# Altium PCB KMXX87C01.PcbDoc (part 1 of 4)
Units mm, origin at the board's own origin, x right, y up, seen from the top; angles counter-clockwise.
Board outline 109.2 x 85.1 mm, 4 copper layers (Top Layer, Mid-Layer 1, Mid-Layer 2, Bottom Layer); 294 components, 222 nets, 951 pads, 352 vias.
Unrouted connection lines stored in the file: 266.
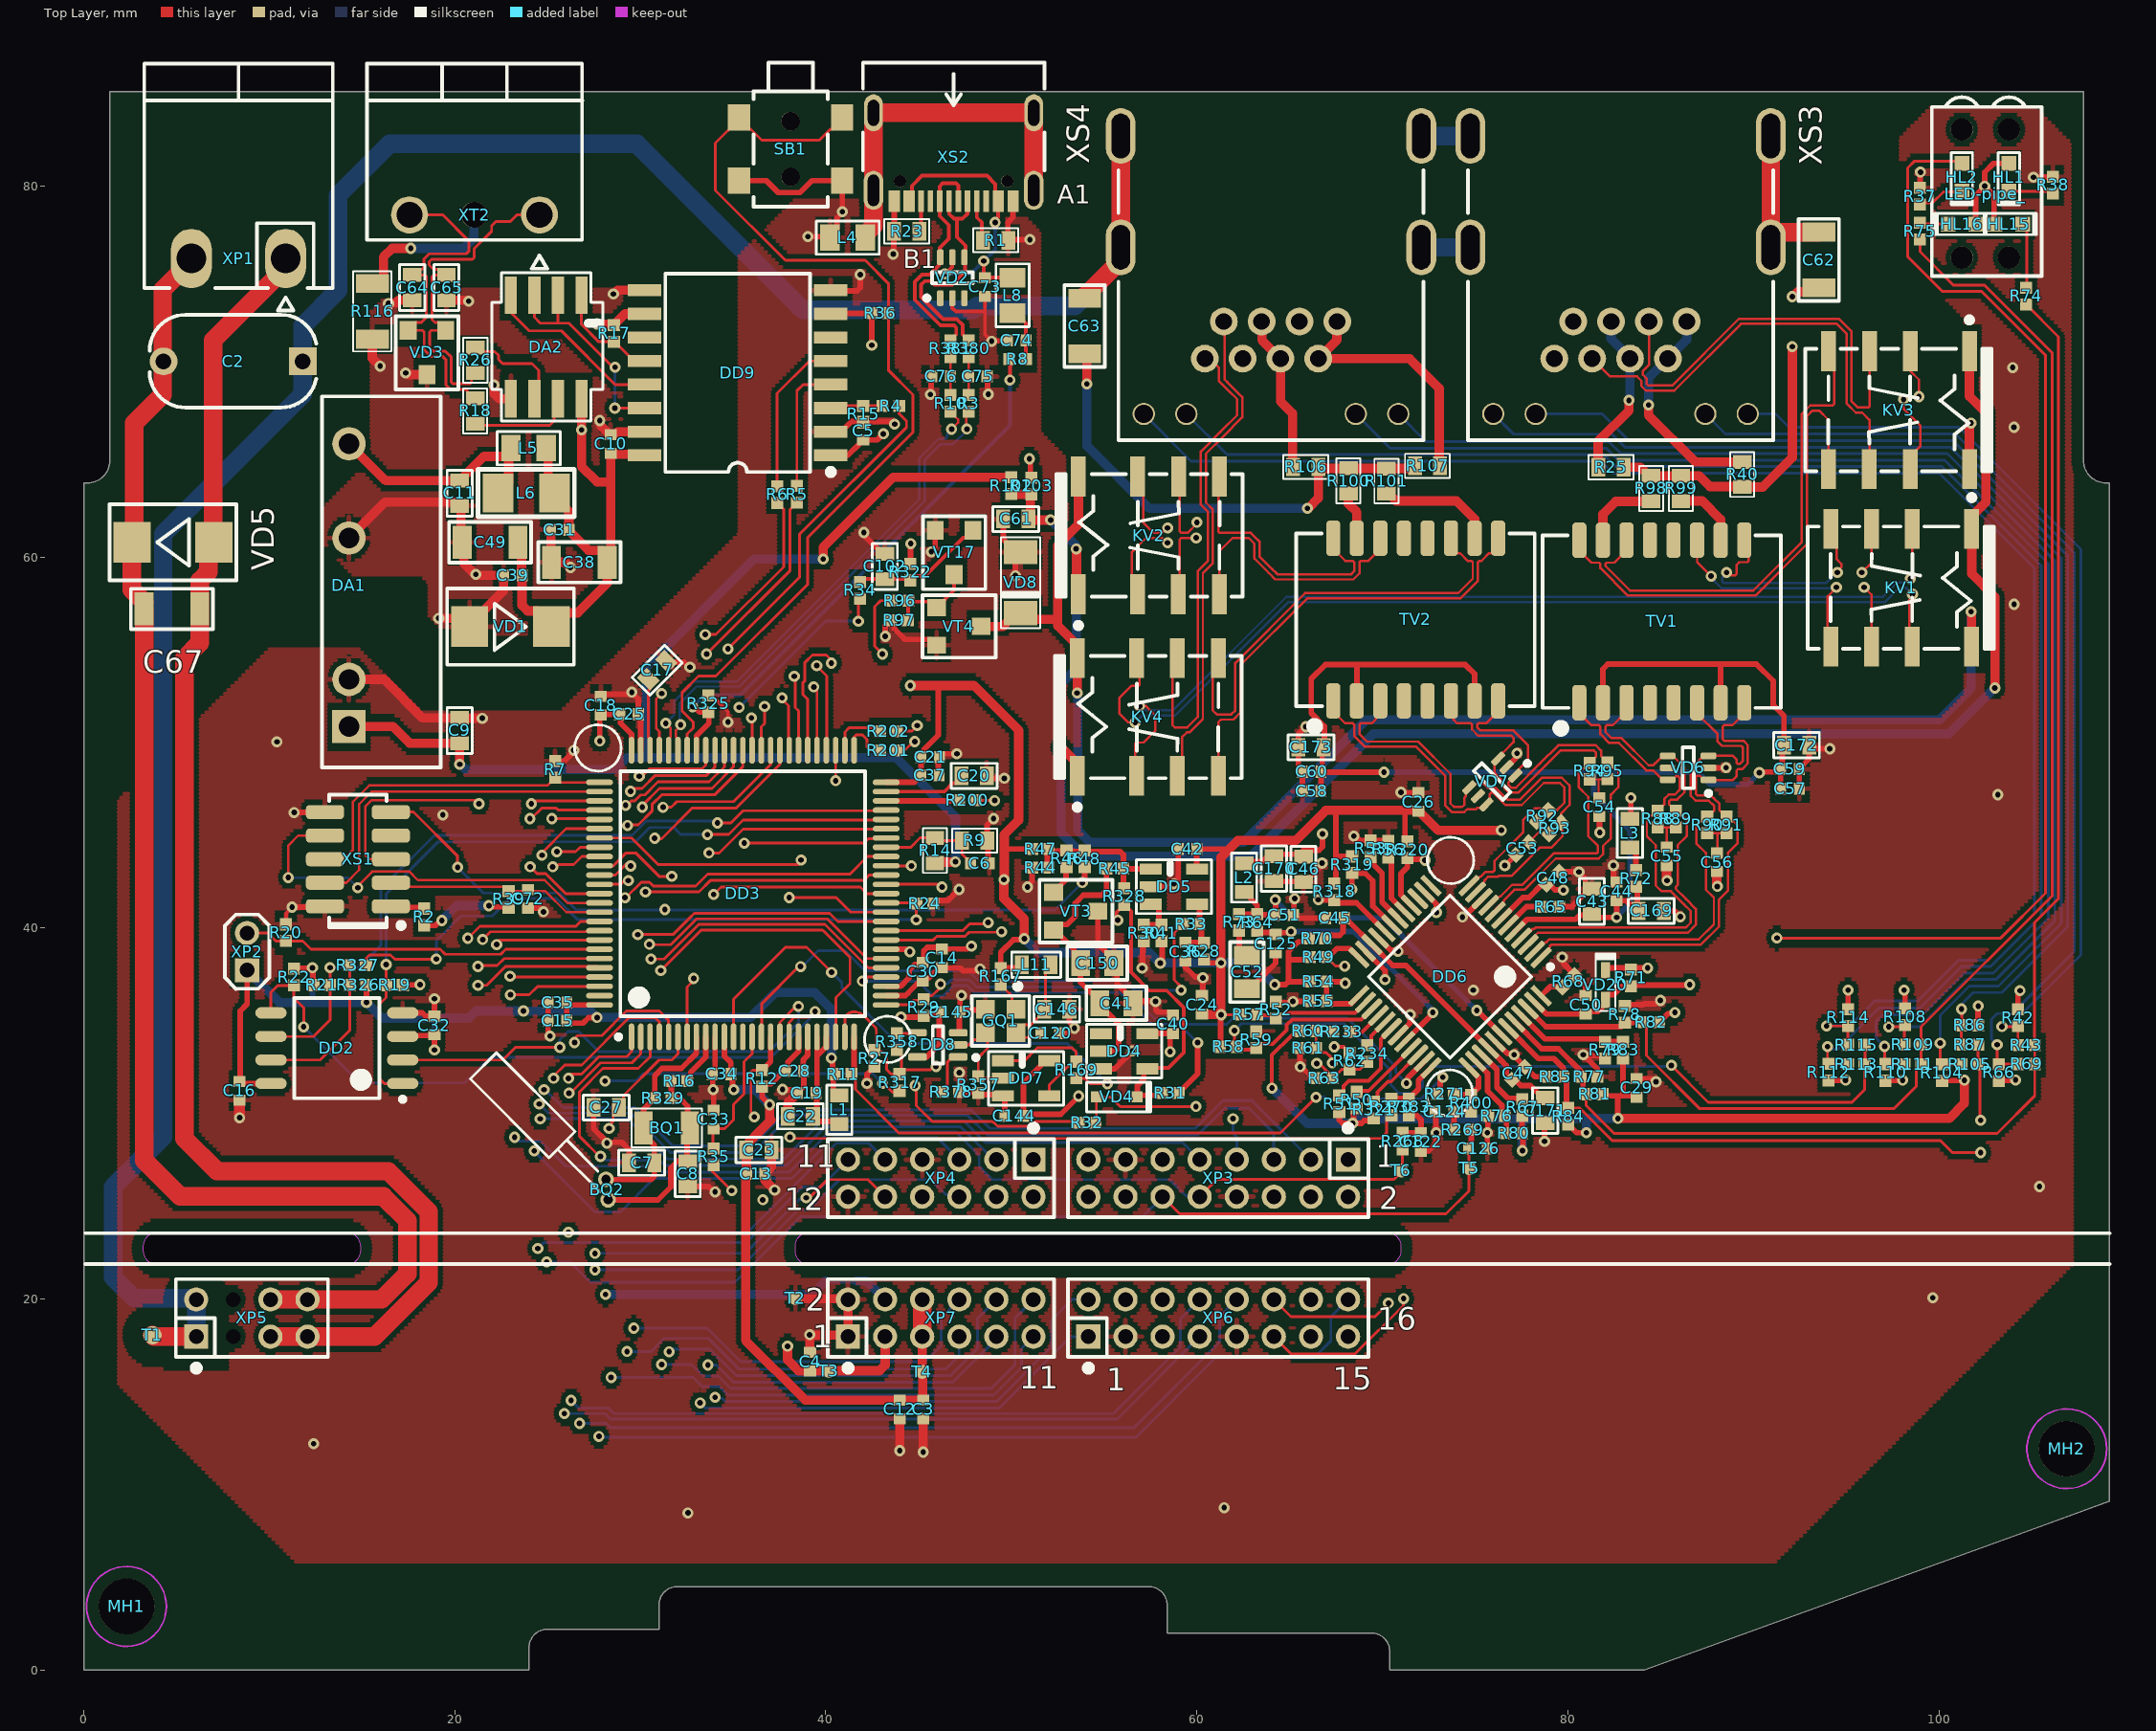
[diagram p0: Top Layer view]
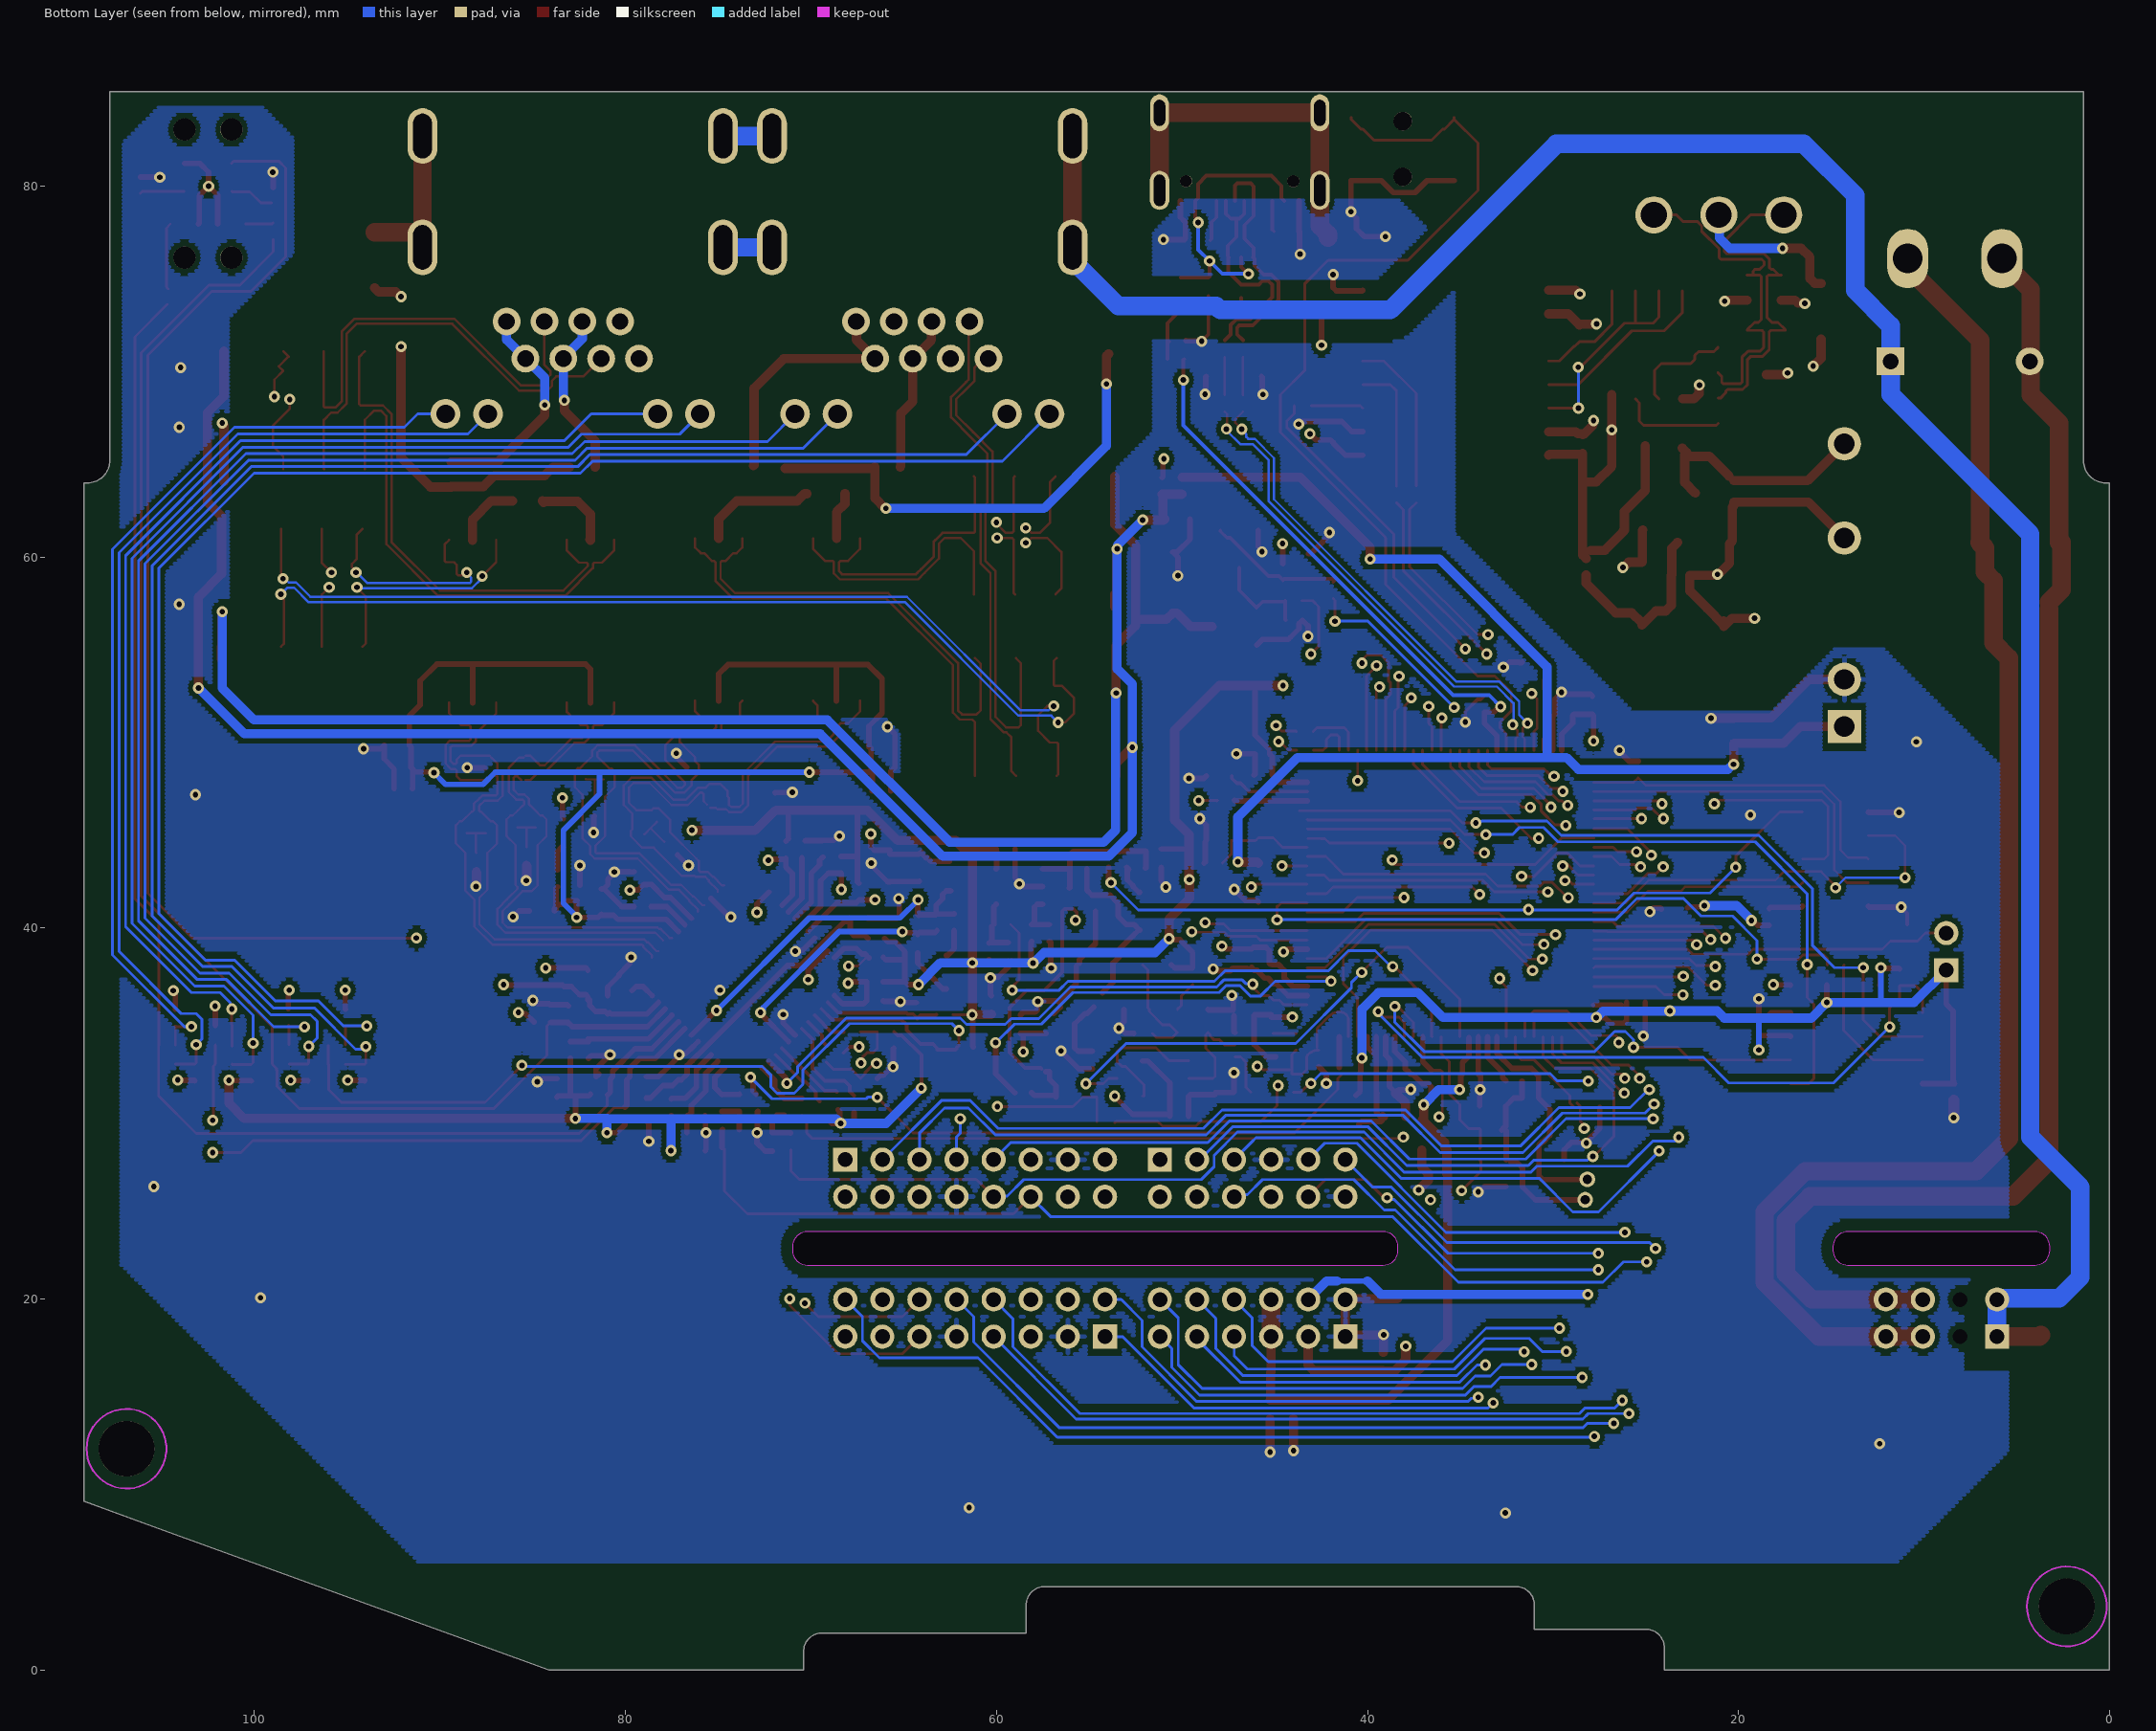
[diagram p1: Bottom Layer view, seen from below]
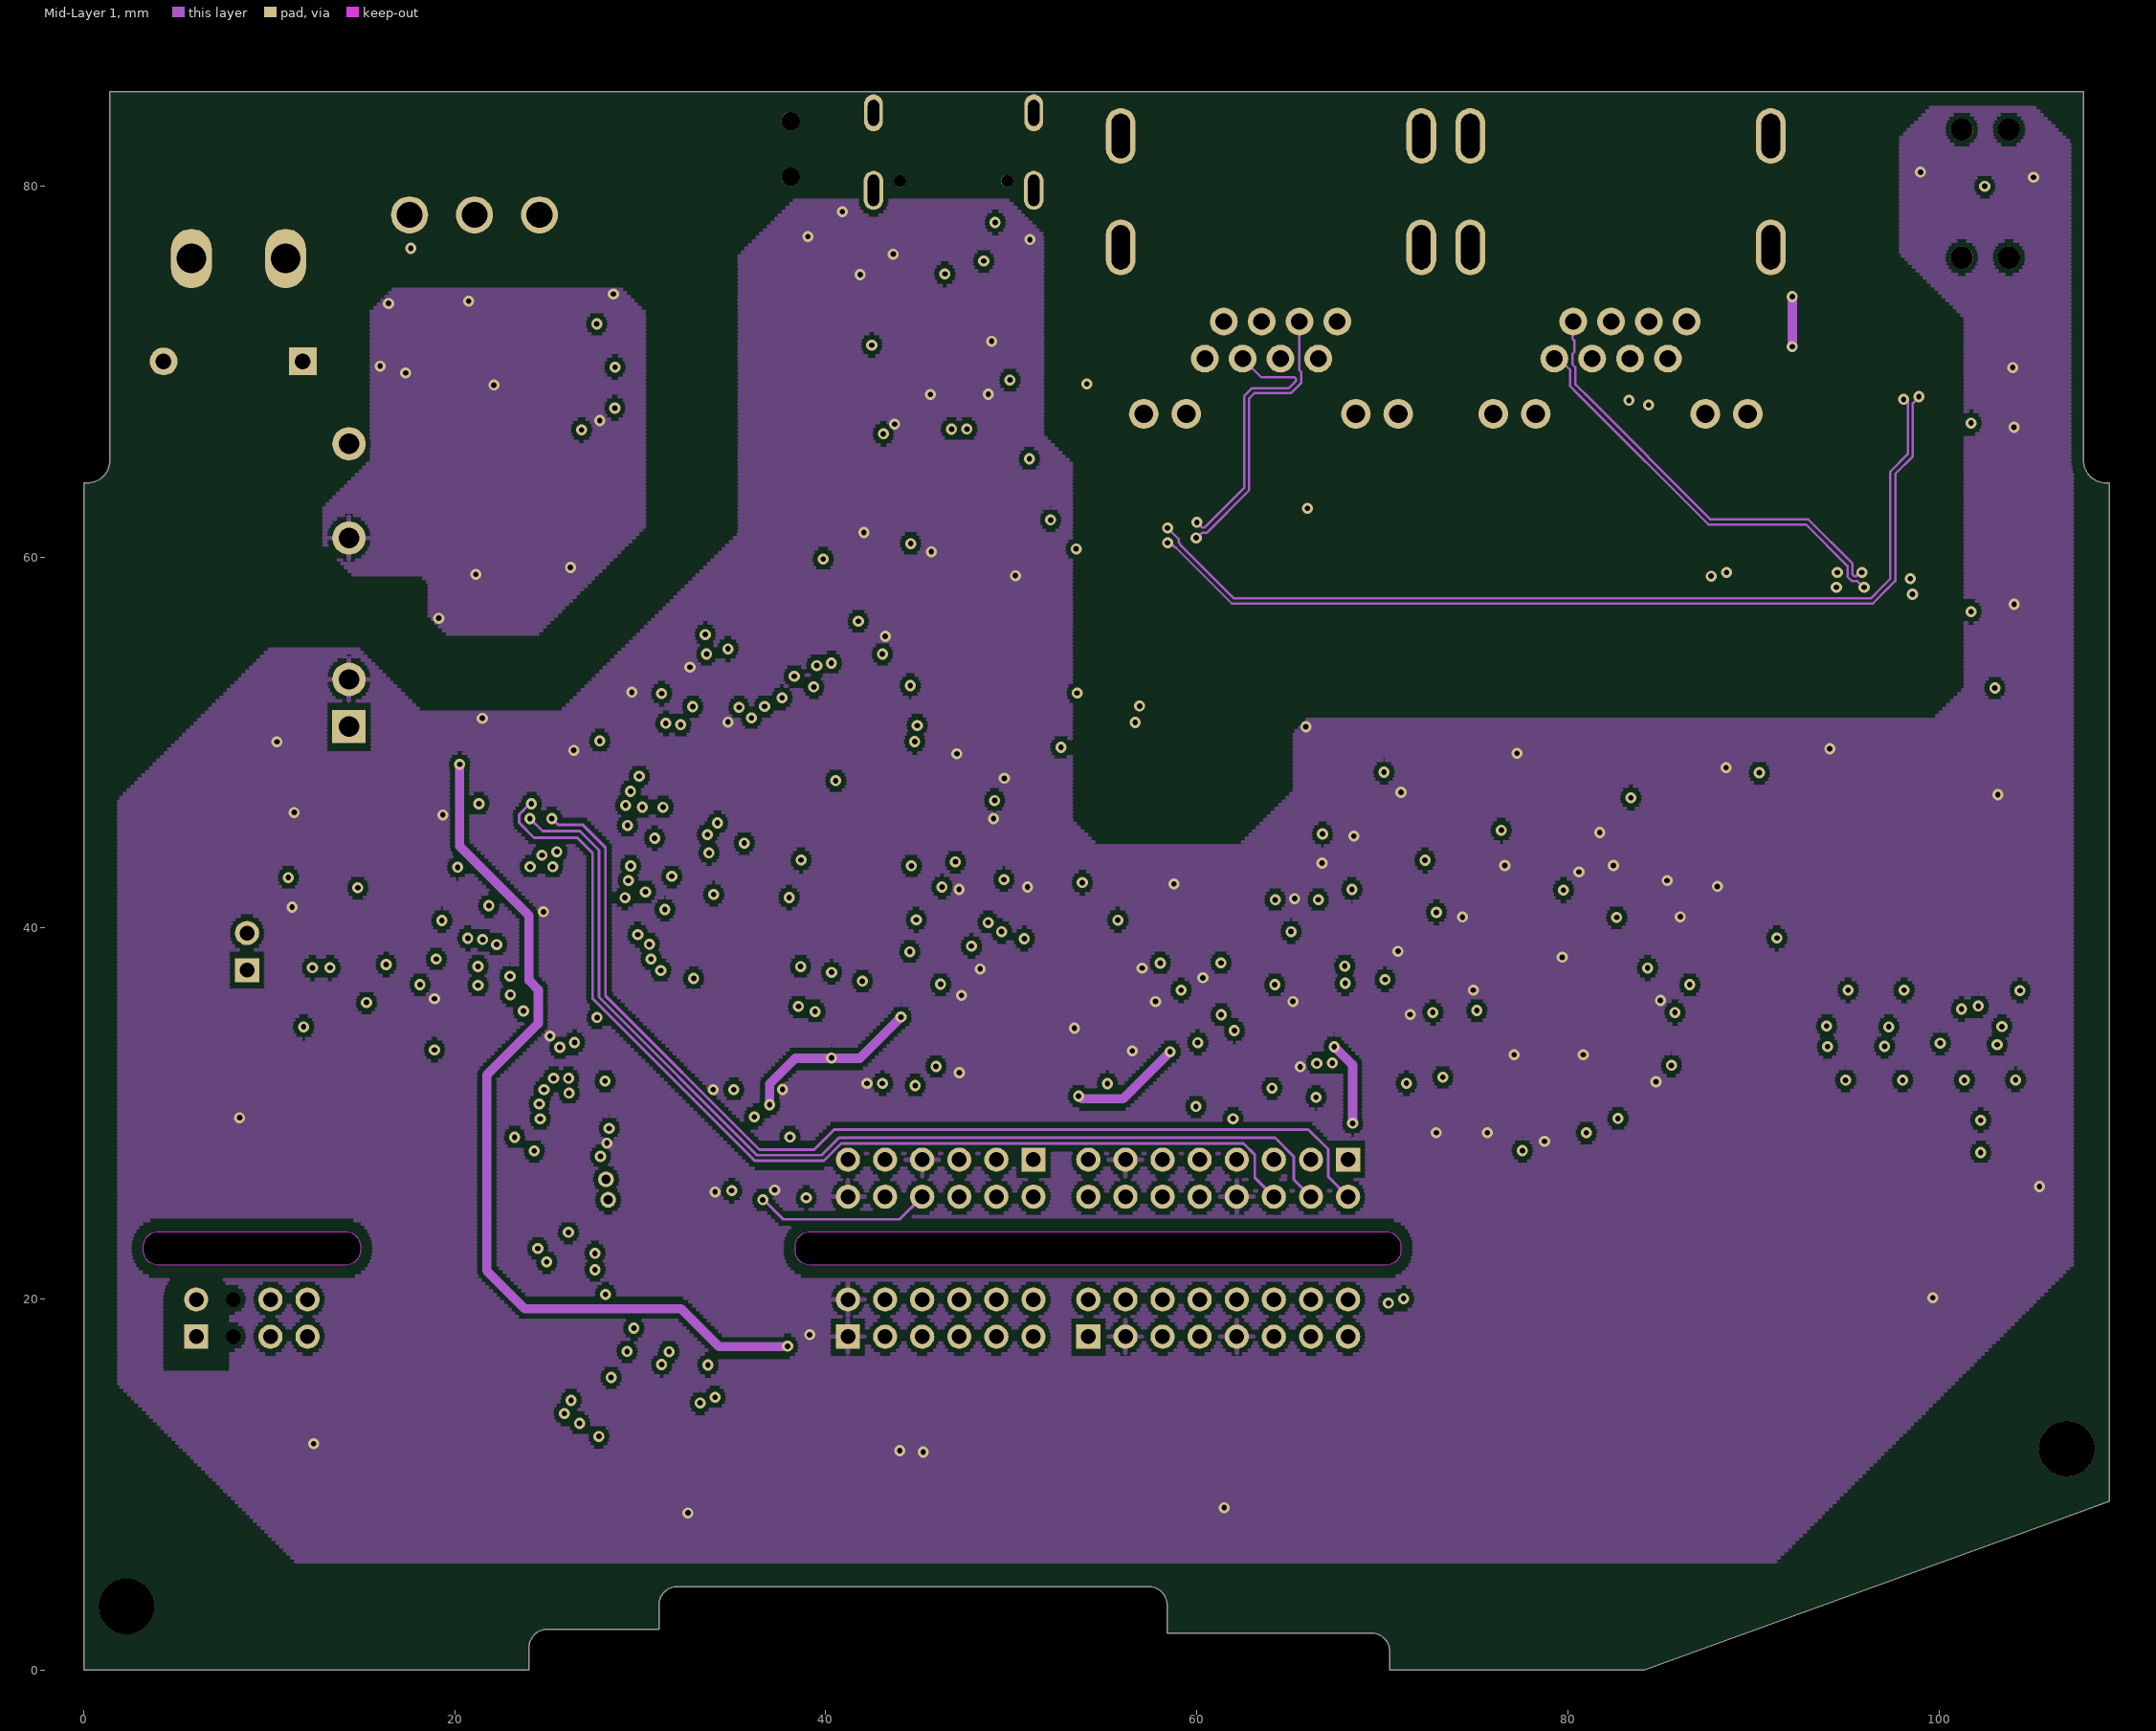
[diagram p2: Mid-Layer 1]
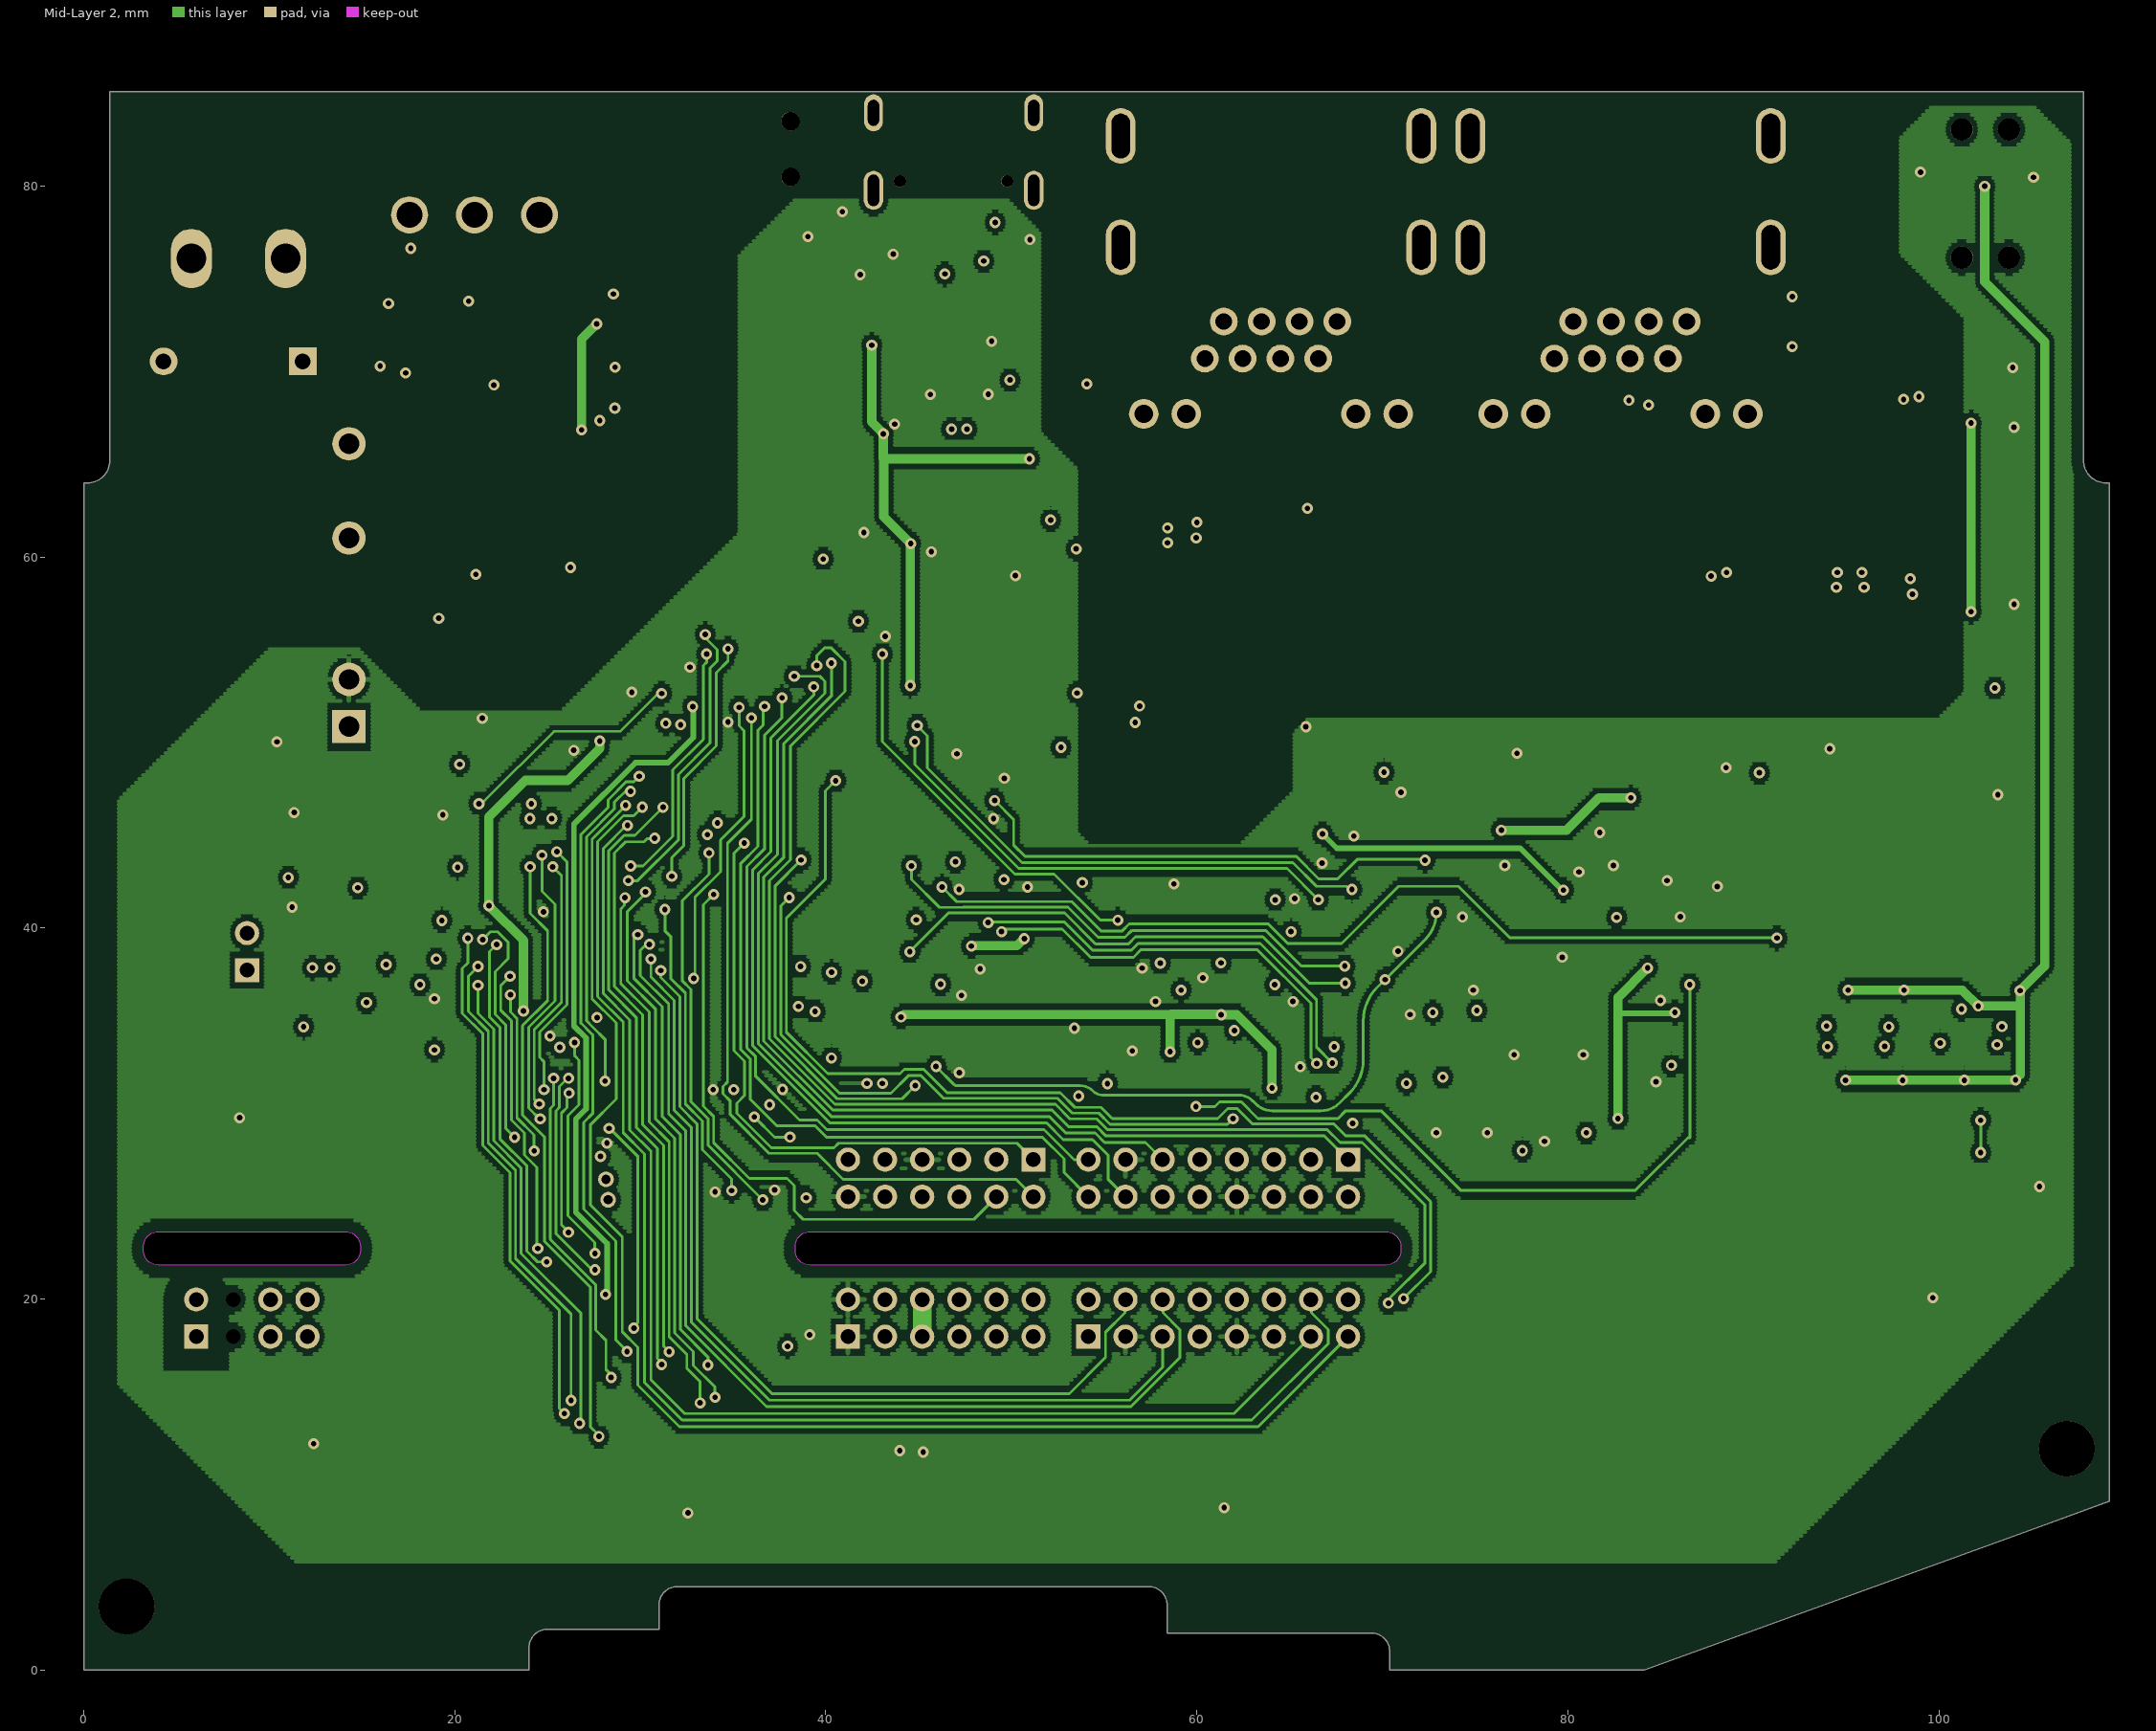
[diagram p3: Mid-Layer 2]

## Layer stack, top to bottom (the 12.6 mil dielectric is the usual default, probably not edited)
Top Solder: solder mask 0.0102, Solder Resist, Dk 3.5
Top Layer: signal copper 0.0356
Dielectric 1: core 0.32, FR-4, Dk 4.8
Mid-Layer 1: signal copper 0.0356
Dielectric2: prepreg 0.32, FR-4, Dk 4.8
Mid-Layer 2: signal copper 0.0356
Dielectric 3: core 0.32, FR-4, Dk 4.8
Bottom Layer: signal copper 0.0356
Bottom Solder: solder mask 0.0102, Solder Resist, Dk 3.5

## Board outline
0,0 24,0 24,1.2 cw(c25,1.2) 25,2.2 31,2.2 31,3.5 cw(c32,3.5) 32,4.5 57.4,4.5 cw(c57.4,3.5) 58.4,3.5 58.4,2 69.4,2 cw(c69.4,1) 70.4,1 70.4,0 84.124,0 105.476,7.748 109.2,9.1 109.2,64 109,64 cw(c109,65.2) 107.8,65.2 107.8,85.1 1.4,85.1 1.4,65.2 cw(c0.2,65.2) 0.2,64 0,64
cut-out: 39.15,21.826 cw(c39.15,22.626) 38.35,22.626 38.35,22.826 cw(c39.15,22.826) 39.15,23.626 70.198,23.626 cw(c70.198,22.826) 70.998,22.826 70.998,22.626 cw(c70.198,22.626) 70.198,21.826
cut-out: 4.015,21.826 cw(c4.015,22.626) 3.215,22.626 3.215,22.826 cw(c4.015,22.826) 4.015,23.626 14.105,23.626 cw(c14.105,22.826) 14.905,22.826 14.905,22.626 cw(c14.105,22.626) 14.105,21.826

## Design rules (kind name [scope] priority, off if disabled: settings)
AssemblyTestPointUsage [(ObjectKind = 'Pad') And (Component Like 'T*') And (AsMM(HoleDiameter) = 0) And (PadShape_AllLayers = 'Round') And ((AsMM(PadXSize_AllLayers) = 0.75) or (AsMM(PadXSize_AllLayers) = 0.991)) And ((AsMM(PadYSize_AllLayers) = 0.75) or (AsMM(PadYSize_AllLayers) = 0.991))] p1:
AssemblyTestpoint [All] p1 off: testpointundercomponent=TRUE minsize=0.75 maxsize=1 preferedsize=0.75 minholesize=0 maxholesize=0 preferedholesize=0 testpointgrid=0.025 usegrid=FALSE gridtolerance=0 allowsidetop=TRUE allowsidebottom=TRUE
BoardOutlineClearance [All    xor  ((Layer = 'BottomOverlay') or           (Layer = 'TopOverlay'))] p1: gap=0.6 ignorepadtopadclearanceinfootprint=FALSE
Clearance "Clearance TP to TP" [(Component Like 'T*') and (not (Component Like 'TV*')) vs (Component Like 'T*') and (not (Component Like 'TV*'))] p1: gap=1.75 ignorepadtopadclearanceinfootprint=FALSE except(0: Arc-Hole Track-Hole SMDPad-Hole THPad-Hole Via-Hole Fill-Hole Poly-Hole Region-Hole Text-Hole)
Clearance CHASSI_to_All [InNet('CHASSI') vs All xor ((ObjectKind = 'Track') And (Layer = 'KeepOutLayer') And (ObjectKind = 'Pad') And (Layer = 'MultiLayer') And (Net = 'No Net'))] p2: gap=1.1 ignorepadtopadclearanceinfootprint=FALSE except(0: Arc-Hole Track-Hole SMDPad-Hole THPad-Hole Via-Hole Fill-Hole Poly-Hole Region-Hole Text-Hole)
Clearance "Clearance_Board Outline" [OnLayer('Board Outline') vs (OnLayer('Mid-Layer 1') or OnLayer('Mid-Layer 2') ) xor ((ObjectKind = 'Pad') And ((Component <> 'SB1') or (Component <> 'XS2')) )] p3 off: gap=0.8 ignorepadtopadclearanceinfootprint=FALSE except(0: Arc-Hole Track-Hole SMDPad-Hole THPad-Hole Via-Hole Fill-Hole Poly-Hole Region-Hole Text-Hole)
Clearance "Clearance Via to Via" [IsVia vs IsVia] p4: gap=0.2 ignorepadtopadclearanceinfootprint=FALSE except(0: Arc-Hole Track-Hole SMDPad-Hole THPad-Hole Via-Hole Fill-Hole Poly-Hole Region-Hole Text-Hole)
Clearance "Clearance Pad to Via (exclude TP)" [IsPad and (not((ObjectKind = 'Pad') And ((Component Like 'T*') or (Component Like 'DA*')))) vs IsVia] p5: gap=0.2 ignorepadtopadclearanceinfootprint=FALSE except(0: Arc-Hole Track-Hole SMDPad-Hole THPad-Hole Via-Hole Fill-Hole Poly-Hole Region-Hole Text-Hole)
Clearance "Clearance Polygon to All" [InPolygon] p6: gap=0.25 ignorepadtopadclearanceinfootprint=FALSE except(0: Arc-Hole Track-Hole SMDPad-Hole THPad-Hole Via-Hole Fill-Hole Poly-Hole Region-Hole Text-Hole)
Clearance Clearance_'RS485' [InNetClass('RS485') vs InNetClass('All Nets')  xor    InNetClass('RS485')] p7: gap=2 ignorepadtopadclearanceinfootprint=FALSE except(0: Arc-Hole Track-Hole SMDPad-Hole THPad-Hole Via-Hole Fill-Hole Poly-Hole Region-Hole Text-Hole)
Clearance Clearance_'Ethernet [InNetClass('Ethernet') vs (InNetClass('All Nets')) xor (InNetClass('Ethernet'))] p8: gap=1.1 ignorepadtopadclearanceinfootprint=FALSE except(0: Arc-Hole Track-Hole SMDPad-Hole THPad-Hole Via-Hole Fill-Hole Poly-Hole Region-Hole Text-Hole)
Clearance "Clearance_All to All" [All] p9: gap=0.15 ignorepadtopadclearanceinfootprint=FALSE
ComponentClearance [All] p1: gap=0.1 collisioncheckmode=3 verticalgap=0.1 showdistances=FALSE
DiffPairsRouting [InDifferentialPairClass('USB')] p1: maxlimit=0.15 minlimit=0.15 mostfreqgap=0.15 toplayer_minwidth=0.127 toplayer_maxwidth=0.127 toplayer_prefwidth=0.127 midlayer1_minwidth=0.127 midlayer1_maxwidth=0.127 midlayer1_prefwidth=0.127 midlayer2_minwidth=0.127 midlayer2_maxwidth=0.127 midlayer2_prefwidth=0.127 bottomlayer_minwidth=0.127 bottomlayer_maxwidth=0.127 bottomlayer_prefwidth=0.127 maxuncoupledlength=12.7
DiffPairsRouting DiffPairsRouting_Eth_IN [All] p2: maxlimit=0.5 minlimit=0.15 mostfreqgap=0.15 toplayer_minwidth=0.127 toplayer_maxwidth=0.381 toplayer_prefwidth=0.127 midlayer1_minwidth=0.127 midlayer1_maxwidth=0.381 midlayer1_prefwidth=0.127 midlayer2_minwidth=0.127 midlayer2_maxwidth=0.381 midlayer2_prefwidth=0.127 bottomlayer_minwidth=0.127 bottomlayer_maxwidth=0.381 bottomlayer_prefwidth=0.127 maxuncoupledlength=12.7
FabricationTestPointUsage [All] p1 off: valid=0 allowmultiple=FALSE
FabricationTestpoint [All] p1 off: side=3 testpointundercomponent=TRUE minsize=1.016 maxsize=2.54 preferedsize=1.524 minholesize=0 maxholesize=1.016 preferedholesize=0.813 testpointgrid=0.025 allowsidetop=TRUE allowsidebottom=TRUE usegrid=TRUE gridtolerance=0
FanoutControl Fanout_BGA [IsBGA] p1 off: bgadir=Out bgaviamode=Centered fanoutstyle=Auto fanoutdirection=Alternating viagrid=0.025 // Fanout_BGA (Default Rule)
FanoutControl Fanout_LCC [IsLCC] p2 off: bgadir=Out bgaviamode=Centered fanoutstyle=Auto fanoutdirection=Alternating viagrid=0.025 // Fanout_LCC (Default Rule)
FanoutControl Fanout_SOIC [IsSOIC] p3 off: bgadir=Out bgaviamode=Centered fanoutstyle=Auto fanoutdirection=Alternating viagrid=0.025 // Fanout_SOIC (Default Rule)
FanoutControl Fanout_Small [(CompPinCount < 5)] p4 off: bgadir=Out bgaviamode=Centered fanoutstyle=Auto fanoutdirection=OutThenIn viagrid=0.025 // Fanout_Small (Default Rule)
FanoutControl Fanout_Default [All] p5 off: bgadir=Out bgaviamode=Centered fanoutstyle=Auto fanoutdirection=Alternating viagrid=0.025 // Fanout_Default (Default Rule)
Height [All] p1 off: minheight=0 maxheight=25.4 prefheight=12.7
HoleSize [All] p1 off: absolutevalues=TRUE maxlimit=2.54 minlimit=0.025 maxpercent=80.000 minpercent=20.000
HoleToHoleClearance [All] p1 off: gap=0.7 allowstackedmicrovias=TRUE
MinimumSolderMaskSliver [All] p1 off: minsoldermaskwidth=0.2
PasteMaskExpansion [All] p1: expansion=-0.03
PlaneClearance [All] p1: clearance=0.5
PlaneConnect [All] p1: planeconnectstyle=Relief reliefexpansion=0.5 reliefentries=4 reliefconductorwidth=0.2 reliefairgap=0.2
PolygonConnect PolygonConnect_Via [IsVia] p1: connectstyle=Direct reliefconductorwidth=0.254 reliefentries=4 polygonreliefangle="90 Angle" airgapwidth=0.254
PolygonConnect PolygonConnect_power [InPadClass('Term')] p2: connectstyle=Direct reliefconductorwidth=0.254 reliefentries=4 polygonreliefangle="90 Angle" airgapwidth=0.254
PolygonConnect PolygonConnect_0.6 [InPadClass('0.6')] p3: connectstyle=Relief reliefconductorwidth=0.6 reliefentries=4 polygonreliefangle="90 Angle" airgapwidth=0.3
PolygonConnect PolygonConnect_1.0 [InPadClass('1.0')] p4: connectstyle=Relief reliefconductorwidth=0.6 reliefentries=4 polygonreliefangle="90 Angle" airgapwidth=0.3
PolygonConnect "PolygonConnect to Thermal components" [(InComponentClass('Thermal connect'))] p5: connectstyle=Relief reliefconductorwidth=0.25 reliefentries=4 polygonreliefangle="90 Angle" airgapwidth=0.25
PolygonConnect PolygonConnect_All [All] p6: connectstyle=Relief reliefconductorwidth=0.25 reliefentries=4 polygonreliefangle="90 Angle" airgapwidth=0.25
RoutingVias [All] p1: holewidth=0.4 width=0.8 viastyle="Through Hole" minholewidth=0.2 minwidth=0.4 maxholewidth=0.8 maxwidth=1.5
SilkToSilkClearance [All] p1: silktosilkclearance=0.1
SilkToSolderMaskClearance SilkscreenOverComponentPads [IsPad] p1: minsilkscreentomaskgap=0.1 clearancetoexposedcopper=TRUE
SolderMaskExpansion Via_0.6x0.3_NoMask [(ObjectKind = 'Via') And (ViaDiameter = AsMM(0.6)) And (HoleDiameter = AsMM(0.3))] p1: expansion=-20 istentingtop=FALSE
SolderMaskExpansion [All] p2: expansion=0 istentingtop=FALSE
Width [All] p1: maxlimit=10 minlimit=0.127 preferedwidth=0.2
10 further rules are at their usual default settings.

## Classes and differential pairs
net class RS485: 5V_RS GND_RS NetC11_1 NetDA2_1 NetDA2_2 NetDA2_4 NetDA2_6 NetDA2_7 NetR116_2 RS485_N RS485_P
net class Ethernet: ETH1_RX_N ETH1_RX_P ETH1_TX_N ETH1_TX_P ETH2_RX_N ETH2_RX_P ETH2_TX_N ETH2_TX_P NetC62_1 NetC63_1 NetR25_2 NetR40_2 NetR98_2 NetR99_2 NetR100_2 NetR101_2 NetR106_2 NetR107_2 RX_N RX_P TV1_RX_N TV1_RX_P TV1_TX_N TV1_TX_P TV2_RX_N TV2_RX_P TV2_TX_N TV2_TX_P TX_N TX_P
component class RS-485: C5 C9 C10 C11 C31 C38 C39 C49 C64 C65 DA1 DA2 DD9 L5 L6 R4 R5 R6 R15 R17 R18 R26 VD1 VD3
component class KMXX87C01_Main: C2 C3 C4 C62 C63 C67 L4 R1 R2 R23 R25 R40 R42 R43 R66 R69 R86 R87 R104 R105 R106 R107 R108 R109 R110 R111 R112 R113 R114 R115 R116 T1 T2 T3 T4 T5 T6 VD5 XP1 XP3 XP4 XP5 XP6 XP7 XS1 XS2 XS3 XS4 XT2
component class Ethernet: C43 C44 C45 C46 C47 C48 C50 C51 C52 C53 C54 C55 C56 C57 C58 C59 C60 C61 C102 C122 C124 C125 C126 C169 C170 C171 C172 C173 DD6 HL15 HL16 KV1 KV2 KV3 KV4 L2 L3 R34 R49 R50 R51 R52 R53 R54 R55 R56 R57 R58 R59 R60 R61 R62 R63 R64 R65 R67 R68 R70 R71 R72 R73 R74 R75 R76 R77 R78 R79 R80 R81 R82 R83 R84 R85 R88 R89 R90 R91 R92 R93 R94 R95 R96 R97 R98 R99 R100 R101 R102 R103 R106 R107 R108 R109 R110 R111 R114 R233 R234 R268 R269 R270 R271 R318 R319 R320 R321 R322 R383 R400 TV1 TV2 VD6 VD7 VD8 VD20 VT4 VT17
component class CPU: BQ1 BQ2 C6 C7 C8 C12 C13 C14 C15 C16 C17 C18 C19 C20 C21 C22 C23 C24 C25 C26 C27 C28 C29 C30 C32 C33 C34 C35 C36 C37 C40 C41 C42 C72 C73 C74 C75 C76 C120 C144 C145 C146 C150 DD2 DD3 DD4 DD5 DD7 DD8 GQ1 HL1 HL2 L1 L8 L11 R3 R7 R8 R9 R10 R11 R12 R14 R16 R19 R20 R21 R22 R24 R27 R28 R29 R30 R31 R32 R33 R35 R36 R37 R38 R39 R41 R44 R45 R46 R47 R48 R167 R200 R201 R202 R317 R325 R326 R327 R328 R329 R357 R358 R378 R380 R381 SB1 VD2 VD4 VT3 XP2
net class CHASSI: CHASSI
differential pair ETH2_TX: +ETH2_TX_P -ETH2_TX_N
differential pair ETH2_RX: +ETH2_RX_P -ETH2_RX_N
differential pair OTG_FS_D: +OTG_FS_D_P -OTG_FS_D_N
differential pair TX: +TX_P -TX_N
differential pair TV2_TX: +TV2_TX_P -TV2_TX_N
differential pair TV2_RX: +TV2_RX_P -TV2_RX_N
differential pair TV1_TX: +TV1_TX_P -TV1_TX_N
differential pair TV1_RX: +TV1_RX_P -TV1_RX_N
differential pair TD2: +TD2_P -TD2_N
differential pair TD1: +TD1_P -TD1_N
differential pair RX: +RX_P -RX_N
differential pair RS485: +RS485_P -RS485_N
differential pair RD2: +RD2_P -RD2_N
differential pair RD1: +RD1_P -RD1_N
differential pair ETH1_TX: +ETH1_TX_P -ETH1_TX_N
differential pair ETH1_RX: +ETH1_RX_P -ETH1_RX_N
differential pair D1: +D1_P -D1_N

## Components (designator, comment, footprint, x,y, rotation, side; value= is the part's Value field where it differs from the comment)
BQ1 "NX3215SA-32,768kHz±10ppm(25C)/±170ppm(-40/+85C)/6" NX3215SA 31.425,29.225 r180 top
BQ2 "MMTF32-32,768kHz±20ppm(25C)/±170ppm(-40/+85C)/6pF" MMTF32 28.15,26.454 r315 top locked
C2 "CS-JY-Y2-1000пФ-20%-Y5U (Murata, 7.0x5.0x7.5)" JY_8-A2 8.05,70.55 r180 top
C3 "C0402-16В-0,1мкФ-10%-X7R (Walsin, 0402B104K160CT)" C0402 45.25,14.05 r270 top
C4 "C0402-16В-0,1мкФ-10%-X7R (Walsin, 0402B104K160CT)" C0402 39.15,16.625 r270 top
C5 "C0402-16В-0,1мкФ-10%-X7R (Samsung, CL05B104KO5NNNC" C0402 42.015,66.817 r270 top
C6 "C0402-50В-0,01мкФ-10%-X7R (Walsin, 0402B103K500CT)" C0402 48.306,43.499 r0 top
C7 "C0603-50В-4,7пФ-0,25пФ-NPO (Walsin, 0603N4R7C500CT)" CC0603-KL 30.075,27.35 r180 top
C8 "C0603-50В-4,7пФ-0,25пФ-NPO (Walsin, 0603N4R7C500CT)" CC0603-KL 32.55,26.75 r270 top
C9 "C0603-25В-1,0мкФ-10%-X7R (Samsung, CL10B105KA8NNNC" CC0603-KL 20.262,50.65 r90 top
C10 "C0402-16В-0,1мкФ-10%-X7R (Samsung, CL05B104KO5NNNC" C0402 28.4,66.1 r270 top
C11 "C0603-25В-1,0мкФ-10%-X7R (Samsung, CL10B105KA8NNNC" CC0603-KL 20.262,63.442 r270 top
C12 "C0402-50В-220пФ-5%-NPO (Walsin, 0402N221J500CT)" C0402 43.995,14.05 r270 top
C13 "C0402-50В-220пФ-5%-NPO (Walsin, 0402N221J500CT)" C0402 36.225,26.75 r0 top
C14 "C0402-50В-220пФ-5%-NPO (Walsin, 0402N221J500CT)" C0402 46.25,38.375 r270 top
C15 "C0402-50В-220пФ-5%-NPO (Walsin, 0402N221J500CT)" C0402 25.531,35.001 r180 top
C16 "C0402-16В-0,1мкФ-10%-X7R (Walsin, 0402B104K160CT)" C0402 8.4,31.225 r270 top
C17 "C0603-10В-2,2мкФ-10%-X7R (Samsung, CL10B225KP8NNNC" CC0603-KL 30.912,53.9 r45 top
C18 "C0402-50В-220пФ-5%-NPO (Walsin, 0402N221J500CT)" C0402 27.875,52 r90 top
C19 "C0402-50В-0,01мкФ-10%-X7R (Walsin, 0402B103K500CT)" C0402 38.975,31.1 r180 top
C20 "C0603-10В-2,2мкФ-10%-X7R (Samsung, CL10B225KP8NNNC" CC0603-KL 47.996,48.204 r0 top
C21 "C0402-50В-220пФ-5%-NPO (Walsin, 0402N221J500CT)" C0402 45.625,49.225 r0 top
C22 "C0603-25В-1,0мкФ-10%-X7R (Samsung, CL10B105KA8NNNC" CC0603-KL 38.625,29.85 r180 top
C23 "C0603-6,3В-4,7мкФ-10%-X5R (Samsung, CL10A475KQ8NNN" CC0603-KL 36.395,28.042 r0 top
C24 "C0402-50В-220пФ-5%-NPO (Walsin, 0402N221J500CT)" C0402 60.275,35.863 r90 top
C25 "C0402-16В-0,1мкФ-10%-X7R (Walsin, 0402B104K160CT)" C0402 29.387,51.525 r0 top
C26 "C0402-50В-220пФ-5%-NPO (Walsin, 0402N221J500CT)" C0402 71.948,46.8 r90 top
C27 "C0603-25В-1,0мкФ-10%-X7R (Samsung, CL10B105KA8NNNC" CC0603-KL 28.157,30.325 r180 top
C28 "C0402-16В-0,1мкФ-10%-X7R (Walsin, 0402B104K160CT)" C0402 38.311,32.29 r0 top
C29 "C0402-50В-220пФ-5%-NPO (Walsin, 0402N221J500CT)" C0402 83.7,31.385 r90 top
C30 "C0402-16В-0,1мкФ-10%-X7R (Walsin, 0402B104K160CT)" C0402 45.225,37.65 r270 top
C31 "C0402-16В-0,1мкФ-10%-X7R (Samsung, CL05B104KO5NNNC" C0402 25.65,61.475 r0 top
C32 "C0402-50В-220пФ-5%-NPO (Walsin, 0402N221J500CT)" C0402 18.9,34.75 r90 top
C33 "C0402-50В-0,01мкФ-10%-X7R (Walsin, 0402B103K500CT)" C0402 33.954,29.678 r90 top
C34 "C0402-16В-0,1мкФ-10%-X7R (Walsin, 0402B104K160CT)" C0402 34.38,32.128 r180 top
C35 "C0402-16В-0,1мкФ-10%-X7R (Walsin, 0402B104K160CT)" C0402 25.531,35.989 r180 top
C36 "C0402-50В-0,01мкФ-10%-X7R (Walsin, 0402B103K500CT)" C0402 59.376,38.725 r270 top
C37 "C0402-16В-0,1мкФ-10%-X7R (Walsin, 0402B104K160CT)" C0402 45.61,48.244 r0 top
C38 "C1206-16В-10мкФ-10%-X7R (Samsung, CL31B106KOHNNNE)" CC1206-KL 26.714,59.725 r0 top
C39 "C0402-16В-0,1мкФ-10%-X7R (Samsung, CL05B104KO5NNNC" C0402 23.127,59.017 r0 top
C40 "C0402-16В-0,1мкФ-10%-X7R (Walsin, 0402B104K160CT)" C0402 58.712,34.813 r90 top
C41 "C0805-16В-10мкФ-10%-X5R (Walsin, 0805X106K160CT)" CC0805-KL 55.66,35.938 r180 top
C42 "C0402-16В-0,1мкФ-10%-X7R (Walsin, 0402B104K160CT)" C0402 59.5,44.266 r180 top
C43 "C0603-25В-1,0мкФ-10%-X7R (Samsung, CL10B105KA8NNNC" CC0603-KL 81.296,41.436 r90 top
C44 "C0402-16В-0,1мкФ-10%-X7R (Walsin, 0402B104K160CT)" C0402 82.615,41.981 r90 top
C45 "C0402-16В-0,1мкФ-10%-X7R (Walsin, 0402B104K160CT)" C0402 67.443,40.537 r180 top
C46 "C0603-25В-1,0мкФ-10%-X7R (Samsung, CL10B105KA8NNNC" CC0603-KL 65.746,43.175 r270 top
C47 "C0402-16В-0,1мкФ-10%-X7R (Walsin, 0402B104K160CT)" C0402 77.337,32.166 r45 top
C48 "C0402-16В-0,1мкФ-10%-X7R (Walsin, 0402B104K160CT)" C0402 79.182,42.691 r45 top
C49 "C1206-16В-10мкФ-10%-X7R (Samsung, CL31B106KOHNNNE)" CC1206-KL 21.9,60.8 r0 top
C50 "C0402-50В-0,01мкФ-10%-X7R (Walsin, 0402B103K500CT)" C0402 80.962,35.863 r90 top
C51 "C0402-16В-0,1мкФ-10%-X7R (Walsin, 0402B104K160CT)" C0402 64.702,40.693 r0 top
C52 "C0805-16В-10мкФ-10%-X5R (Walsin, 0805X106K160CT)" CC0805-KL 62.7,37.624 r90 top
C53 "C0402-16В-0,1мкФ-10%-X7R (Walsin, 0402B104K160CT)" C0402 77.55,44.292 r225 top
C54 "C0402-16В-0,1мкФ-10%-X7R (Walsin, 0402B104K160CT)" C0402 81.689,46.524 r270 top
C55 "C0402-16В-0,1мкФ-10%-X7R (Walsin, 0402B104K160CT)" C0402 85.331,43.872 r270 top
C56 "C0402-16В-0,1мкФ-10%-X7R (Walsin, 0402B104K160CT)" C0402 88.035,43.546 r270 top
C57 "C0402-16В-0,1мкФ-10%-X7R (Walsin, 0402B104K160CT)" C0402 91.978,47.514 r0 top
C58 "C0402-16В-0,1мкФ-10%-X7R (Walsin, 0402B104K160CT)" C0402 66.19,47.38 r180 top
C59 "C0402-16В-0,1мкФ-10%-X7R (Walsin, 0402B104K160CT)" C0402 91.973,48.564 r0 top
C60 "C0402-16В-0,1мкФ-10%-X7R (Walsin, 0402B104K160CT)" C0402 66.19,48.43 r180 top
C61 "C0603-25В-1,0мкФ-10%-X7R (Samsung, CL10B105KA8NNNC" CC0603-KL 50.244,62.051 r180 top
C62 "C1206-2000B-1000пФ-10%-X7R (Walsin, 1206B102K202CT" CC1206-KL 93.525,76.02 r90 top
C63 "C1206-2000B-1000пФ-10%-X7R (Walsin, 1206B102K202CT" CC1206-KL 53.954,72.458 r90 top
C64 "Не устанавливать" CC0603-KL 17.698,74.527 r90 top
C65 "Не устанавливать" CC0603-KL 19.548,74.527 r90 top
C67 "C1206-100В-0,1мкФ-10%-X7R (Samsung, CL31B104KCFNNN" CC1206-KL 4.75,57.2 r0 top
C72 "C0402-50В-0,01мкФ-10%-X7R (Walsin, 0402B103K500CT)" C0402 23.95,41.575 r90 top
C73 "C0402-50В-0,01мкФ-10%-X7R (Walsin, 0402B103K500CT)" C0402 48.58,74.564 r90 top
C74 "C0402-16В-0,1мкФ-10%-X7R (Walsin, 0402B104K160CT)" C0402 50.289,71.672 r180 top
C75 "C0402-50В-33пФ-5%-NPO (Walsin, 0402N330J500CT)" C0402 48.19,69.738 r180 top
C76 "C0402-50В-33пФ-5%-NPO (Walsin, 0402N330J500CT)" C0402 46.215,69.738 r0 top
C102 "C0603-25В-1,0мкФ-10%-X7R (Samsung, CL10B105KA8NNNC" CC0603-KL 43.181,59.495 r90 top
C120 "C0402-50В-0,01мкФ-10%-X7R (Walsin, 0402B103K500CT)" C0402 52.1,34.328 r0 top
C122 "C0402-50В-10пФ-5%-NPO (Murata, GRM1555C1H100JA01D)" C0402 72.081,28.471 r270 top
C124 "C0402-50В-10пФ-5%-NPO (Murata, GRM1555C1H100JA01D)" C0402 73.362,30.107 r180 top
C125 "C0402-16В-0,1мкФ-10%-X7R (Walsin, 0402B104K160CT)" C0402 64.249,39.16 r270 top
C126 "C0402-16В-0,1мкФ-10%-X7R (Walsin, 0402B104K160CT)" C0402 75.162,28.107 r0 top
C144 "C0402-16В-0,1мкФ-10%-X7R (Walsin, 0402B104K160CT)" C0402 50.154,29.862 r180 top
C145 "C0402-16В-0,1мкФ-10%-X7R (Walsin, 0402B104K160CT)" C0402 46.744,35.468 r0 top
C146 "C0603-10В-2,2мкФ-10%-X7R (Samsung, CL10B225KP8NNNC" CC0603-KL 52.45,35.625 r0 top
C150 "C0805-16В-10мкФ-10%-X5R (Walsin, 0805X106K160CT)" CC0805-KL 54.629,38.104 r180 top
C169 "C0603-10В-10мкф-10%-X5R (Samsung, CL10A106KP8NNNC)" CC0603-KL 84.5,40.925 r0 top
C170 "C0603-10В-10мкф-10%-X5R (Samsung, CL10A106KP8NNNC)" CC0603-KL 64.153,43.208 r270 top
C171 "C0603-10В-10мкф-10%-X5R (Samsung, CL10A106KP8NNNC)" CC0603-KL 78.78,30.157 r270 top
C172 "C0603-10В-10мкф-10%-X5R (Samsung, CL10A106KP8NNNC)" CC0603-KL 92.328,49.864 r0 top
C173 "C0603-10В-10мкф-10%-X5R (Samsung, CL10A106KP8NNNC)" CC0603-KL 66.153,49.747 r180 top
DA1 "F0505S-1WR2" F0505S-1W 14.291,50.867 r90 top value="F0505S-1WR2 (Mornsun, SIP-5)"
DA2 "THVD1500DR (TI, SO-8)" SO8 24.925,71.325 r270 top
DD2 "MX25L3233FM2I-08G (Macronix, SO-8)" SOP127P790X216-8N 13.64,33.524 r180 top locked
DD3 "STM32F207VCT6 (STM, LQFP-100)" TSQFP50P1600X1600X160-100N 35.525,41.857 r90 top locked
DD4 "SN74LVC1G17DBV (Ti,SOT23-5)" SOT23-5 56.085,33.363 r180 top
DD5 "CAT823STDI-GT3 (Onsemi, SOT-23-5)" SOT23-5 58.766,42.232 r180 top
DD6 "KSZ8863RLLI (Micrel, LQFP-48)" TSQFP50P900X900X160-48N 73.65,37.378 r225 top locked
DD7 "SN74LVC1G80DBVR (TI, SOT23-5)" SOT23-5 50.8,31.9 r180 top
DD8 "SN74LVC1G125DCK (Ti, SC70-5)" SOT65P210-5N 46.038,33.704 r180 top locked
DD9 "ISO7331CDWR (TI, SO_W-16)" SO-16_W 35.25,69.938 r180 top
GQ1 "FXO2520-3,3V-50,000MHz±50ppm 15pF (Fronter)" FXO2520 49.425,34.993 r180 top
HL1 "HQ19-2132SYGC82 (HQG)" HT19-2132 103.779,80.476 r90 top
HL2 "HT19-2132SURC-С" HT19-2132 101.239,80.476 r90 top
HL15 "HQ19-2132SYGC82 (HQG)" HT19-2132 103.779,77.956 r180 top
HL16 "HQ19-2132SYGC82 (HQG)" HT19-2132 101.239,77.956 r0 top
KV1 "HFD4/5-SR (Hongfa)" "TE IM03GR Gul wings" 97.975,58.349 r180 top locked
KV2 "HFD4/5-SR (Hongfa)" "TE IM03GR Gul wings" 57.417,61.17 r0 top locked
KV3 "HFD4/5-SR (Hongfa)" "TE IM03GR Gul wings" 97.85,67.925 r180 top locked
KV4 "HFD4/5-SR (Hongfa)" "TE IM03GR Gul wings" 57.357,51.379 r0 top locked
L1 "FB0603-0,2А-2500 Ом (100МГц)-25%-0,8 Ом (Viking)" L0603 40.725,30.2 r90 top
L2 "FB0603-0,2А-2500 Ом (100МГц)-25%-0,8 Ом (Viking)" L0603 62.55,42.725 r270 top
L3 "FB0603-0,2А-2500 Ом (100МГц)-25%-0,8 Ом (Viking)" L0603 83.35,45.125 r90 top
L4 "FB0805-5А-120 Ом (100МГц)-25%-0,02 Ом (INPAQ, MHC2012S121UBP)" L0805 41.175,77.225 r180 top
L5 "FB0805-1,5А-120 Ом (100МГц)-25%-0,03 Ом (Murata, B" L0805 23.975,65.875 r0 top
L6 "1.0uH" L1206 23.85,63.45 r0 top value="Не устанавливать"
L8 "FB0805-5А-120 Ом (100МГц)-25%-0,02 Ом (INPAQ, MHC2012S121UBP)" L0805 50.069,74.108 r270 top
L11 "FB0603-0,2А-2500 Ом (100МГц)-25%-0,8 Ом (Viking)" L0603 51.345,38.018 r0 top
LED-pipe_ "Comment" "HS LC-H-D2C/ R2XC2-2,54" 101.239,80.476 r0 top locked
MH1 "Comment" KOTB30 2.3,3.43 r90 top locked
MH2 "Comment" KOTB30 106.9,11.93 r90 top locked
R1 "RC03-5,1кОм 1%" RC0603-KL 49.155,77.082 r0 top
R2 "RC02-0,0 Ом 5%" R0402 18.35,40.6 r270 top
R3 "RC02-0,0 Ом 5%" R0402 47.69,68.288 r270 top
R4 "RC02-10 Ом 5%" R0402 43.5,68.156 r180 top
R5 "RC02-10 Ом 5%" R0402 38.441,63.385 r90 top
R6 "RC02-10 Ом 5%" R0402 37.375,63.375 r90 top
R7 "RC02-10кОм 1%" R0402 25.407,48.55 r270 top
R8 "RC02-0,0 Ом 5%" R0402 50.339,70.677 r180 top
R9 "RT03-6,65 кОм 1%-25ppm/C" RC0603-KL 48.019,44.717 r0 top
R10 "RC02-0,0 Ом 5%" R0402 46.715,68.288 r270 top
R11 "RC02-1,0кОм 1%" R0402 40.925,32.125 r180 top
R12 "RC02-1,0кОм 1%" R0402 36.565,31.89 r270 top
R14 "RT03-6,65 кОм 1%-25ppm/C" RC0603-KL 45.882,44.182 r90 top
R15 "RC02-10кОм 1%" R0402 42.015,67.706 r90 top
R16 "RC02-0,0 Ом 5%" R0402 32.089,31.758 r180 top
R17 "RC02-10кОм 1%" R0402 28.575,72.059 r90 top
R18 "RC03-10 Ом 5%" RC0603-KL 21.1,67.885 r270 top
R19 "RC02-10кОм 1%" R0402 16.75,36.925 r0 top
R20 "RC02-1,0кОм 1%" R0402 10.9,39.752 r90 top
R21 "RC02-10кОм 1%" R0402 12.825,36.925 r180 top
R22 "RC02-10кОм 1%" R0402 11.325,37.357 r90 top
R23 "RC03-5,1кОм 1%" RC0603-KL 44.365,77.563 r180 top
R24 "RC02-4,7кОм 5%" R0402 45.337,41.316 r0 top
R25 "RC03-75 Ом 5%" RC0603-KL 82.325,64.85 r180 top
R26 "RC03-10 Ом 5%" RC0603-KL 21.106,70.619 r90 top
R27 "RC02-4,7кОм 5%" R0402 42.625,32.975 r270 top
R28 "RC02-10кОм 1%" R0402 60.4,38.75 r90 top
R29 "RC02-4,7кОм 5%" R0402 45.27,35.714 r270 top
R30 "Не устанавливать" R0402 57.147,39.736 r90 top
R31 "RC02-10кОм 1%" R0402 58.56,31.115 r180 top
R32 "RC02-200 Ом 5%" R0402 54.075,29.51 r180 top
R33 "RC02-200 Ом 5%" R0402 59.691,40.206 r180 top
R34 "RC02-200 Ом 5%" R0402 41.847,58.209 r90 top
R35 "RC02-1,0кОм 1%" R0402 33.95,27.669 r270 top
R36 "RC02-10кОм 1%" R0402 42.92,73.158 r180 top
R37 "RC02-1,0кОм 1%" R0402 98.983,79.458 r90 top
R38 "RC02-1,0кОм 1%" R0402 106.15,80.057 r270 top
R39 "RC02-4,7кОм 5%" R0402 22.9,41.55 r270 top
R40 "RC03-75 Ом 5%" RC0603-KL 89.4,64.457 r90 top
R41 "RC02-1,0кОм 1%" R0402 58.1,39.725 r270 top
R42 "RC02-470 Ом 1%" R0402 104.268,35.169 r270 top
R43 "RC02-0,0 Ом 5%" R0402 104.715,33.689 r180 top
R44 "RC02-100кОм 1%" R0402 51.568,43.267 r0 top
R45 "RC02-360кОм 1%" R0402 55.575,43.207 r180 top
R46 "RC02-200 Ом 5%" R0402 52.976,43.735 r270 top
R47 "Не устанавливать" R0402 51.568,44.262 r0 top
R48 "Не устанавливать" R0402 53.954,43.728 r90 top
R49 "RC02-4,7кОм 5%" R0402 66.55,38.425 r180 top
R50 "RC02-4,7кОм 5%" R0402 68.61,30.725 r270 top
R51 "RC02-4,7кОм 5%" R0402 67.679,30.521 r270 top
R52 "Не устанавливать" R0402 64.267,35.587 r270 top
R53 "RC02-1,0кОм 1%" R0402 69.362,44.277 r270 top
R54 "RC02-4,7кОм 5%" R0402 66.546,37.112 r180 top
R55 "Не устанавливать" R0402 66.546,36.073 r180 top
R56 "RC02-1,0кОм 1%" R0402 70.325,44.25 r270 top
R57 "RC02-4,7кОм 5%" R0402 62.8,35.338 r0 top
R58 "RC02-4,7кОм 5%" R0402 61.7,33.6 r0 top
R59 "Не устанавливать" R0402 63.2,33.975 r90 top
R60 "RC02-4,7кОм 5%" R0402 65.975,34.45 r180 top
R61 "Не устанавливать" R0402 65.975,33.525 r180 top
R62 "Не устанавливать" R0402 68.237,32.827 r90 top
R63 "RC02-1,0кОм 1%" R0402 66.875,31.9 r180 top
R64 "RC02-0,0 Ом 5%" R0402 63.25,40.3 r270 top
R65 "RC02-11,8кОм 1%" R0402 79.075,41.15 r0 top
R66 "RC02-470 Ом 1%" R0402 103.225,32.209 r90 top
R67 "RC02-4,7кОм 5%" R0402 77.537,30.332 r90 top
R68 "RC02-1,0кОм 1%" R0402 80.025,37.125 r225 top
R69 "RC02-0,0 Ом 5%" R0402 104.718,32.669 r180 top
R70 "RC02-0,0 Ом 5%" R0402 66.479,39.436 r0 top
R71 "RC02-100кОм 1%" R0402 83.4,37.319 r90 top
R72 "RC02-0,0 Ом 5%" R0402 83.675,42.675 r90 top
R73 "RC02-0,0 Ом 5%" R0402 62.28,40.314 r270 top
R74 "RC02-470 Ом 1%" R0402 104.7,74.075 r90 top
R75 "RC02-470 Ом 1%" R0402 98.983,77.575 r90 top
R76 "RC02-1,0кОм 1%" R0402 76.162,29.882 r0 top
R77 "Не устанавливать" R0402 81.143,31.982 r180 top
R78 "Не устанавливать" R0402 83.075,35.35 r270 top
R79 "RC02-1,0кОм 1%" R0402 82,33.425 r90 top
R80 "Не устанавливать" R0402 77.087,28.932 r180 top
R81 "RC02-4,7кОм 5%" R0402 81.435,31.046 r180 top
R82 "RC02-4,7кОм 5%" R0402 84.475,34.925 r180 top
R83 "RC02-4,7кОм 5%" R0402 82.975,33.425 r90 top
R84 "RC02-4,7кОм 5%" R0402 80.025,29.857 r90 top
R85 "Не устанавливать" R0402 79.314,31.982 r180 top
R86 "RC02-470 Ом 1%" R0402 101.662,34.761 r180 top
R87 "RC02-0,0 Ом 5%" R0402 101.662,33.711 r180 top
R88 "RC02-49,9 Ом 1%" R0402 84.851,45.88 r270 top
R89 "RC02-49,9 Ом 1%" R0402 85.82,45.878 r270 top
R90 "RC02-49,9 Ом 1%" R0402 87.514,45.56 r270 top
R91 "RC02-49,9 Ом 1%" R0402 88.559,45.56 r270 top
R92 "RC02-49,9 Ом 1%" R0402 78.628,46.042 r225 top
R93 "RC02-49,9 Ом 1%" R0402 79.305,45.374 r225 top
R94 "RC02-49,9 Ом 1%" R0402 81.183,48.466 r270 top
R95 "RC02-49,9 Ом 1%" R0402 82.139,48.479 r270 top
R96 "RC02-1,0кОм 1%" R0402 43.991,57.65 r180 top
R97 "RC02-4,7кОм 5%" R0402 43.962,56.597 r180 top
R98 "RC03-75 Ом 5%" RC0603-KL 84.489,63.706 r270 top
R99 "RC03-75 Ом 5%" RC0603-KL 86.095,63.706 r270 top
R100 "RC03-75 Ом 5%" RC0603-KL 68.172,64.106 r270 top
R101 "RC03-75 Ом 5%" RC0603-KL 70.223,64.098 r270 top
R102 "RC02-0,0 Ом 5%" R0402 50,63.85 r270 top
R103 "Не устанавливать" R0402 51.072,63.831 r270 top
R104 "RC02-470 Ом 1%" R0402 100.175,32.2 r90 top
R105 "RC02-0,0 Ом 5%" R0402 101.662,32.661 r180 top
R106 "RC03-75 Ом 5%" RC0603-KL 65.873,64.86 r180 top
R107 "RC03-75 Ом 5%" RC0603-KL 72.434,64.917 r0 top
R108 "RC02-470 Ом 1%" R0402 98.175,35.216 r270 top
R109 "RC02-0,0 Ом 5%" R0402 98.6,33.716 r180 top
R110 "RC02-470 Ом 1%" R0402 97.125,32.217 r90 top
R111 "RC02-0,0 Ом 5%" R0402 98.6,32.659 r180 top
R112 "RC02-470 Ом 1%" R0402 94.05,32.223 r90 top
R113 "RC02-0,0 Ом 5%" R0402 95.547,32.656 r180 top
R114 "RC02-470 Ом 1%" R0402 95.1,35.173 r270 top
R115 "RC02-0,0 Ом 5%" R0402 95.547,33.7 r180 top
R116 "RC06-100 Ом 5%" RC1206-KL 15.55,73.25 r90 top
R167 "Не устанавливать" R0402 49.425,37.4 r90 top
R169 "RC02-0,0 Ом 5%" R0402 53.5,32.35 r90 top
R200 "RC02-22 Ом-1%" R0402 47.633,46.892 r0 top
R201 "RC02-22 Ом-1%" R0402 43.37,49.582 r0 top
R202 "RC02-22 Ом-1%" R0402 43.379,50.6 r0 top
R233 "RC02-22 Ом-1%" R0402 67.8,34.404 r180 top
R234 "RC02-22 Ом-1%" R0402 69.183,33.234 r270 top
R268 "RC02-100 Ом 5%" R0402 71.091,28.506 r270 top
R269 "RC02-100 Ом 5%" R0402 74.322,29.132 r0 top
R270 "RC02-0,0 Ом 5%" R0402 70.487,30.357 r270 top
R271 "RC02-0,0 Ом 5%" R0402 73.404,31.046 r180 top
R317 "Не устанавливать" R0402 43.975,31.675 r90 top
R318 "RC02-4,7кОм 5%" R0402 67.415,41.955 r90 top
R319 "RC02-4,7кОм 5%" R0402 68.372,43.416 r90 top
R320 "RC02-4,7кОм 5%" R0402 71.356,44.221 r90 top
R321 "RC02-4,7кОм 5%" R0402 69.537,30.2 r270 top
R322 "RC02-4,7кОм 5%" R0402 44.551,59.195 r90 top
R325 "RC02-1,0кОм 1%" R0402 33.675,52.092 r270 top
R326 "RC02-10кОм 1%" R0402 14.786,36.925 r0 top
R327 "RC02-0,0 Ом 5%" R0402 14.761,38 r180 top
R328 "Не устанавливать" R0402 56.075,41.7 r90 top
R329 "RC02-0,0 Ом 5%" R0402 31.225,30.833 r0 top
R357 "RC02-10кОм 1%" R0402 48.217,31.552 r90 top
R358 "RC02-22 Ом-1%" R0402 43.835,33.878 r90 top
R378 "RC02-0,0 Ом 5%" R0402 46.744,31.157 r0 top
R380 "RC02-22 Ом-1%" R0402 47.69,71.238 r270 top
R381 "RC02-22 Ом-1%" R0402 46.715,71.238 r270 top
R383 "RC02-0,0 Ом 5%" R0402 71.437,30.357 r270 top
R400 "RC02-0,0 Ом 5%" R0402 74.793,30.559 r270 top
SB1 "TP-1113S1-LR1325 (Tone Parts Electronics)" TP-1113 38.1,82 r90 top locked
T1 "" T17A 3.7,18.05 r0 top
T2 "" T07A 38.365,20.05 r90 top
T3 "" T07A 40.18,16.132 r90 top
T4 "" T07A 45.2,16.075 r90 top
T5 "" T07A 74.702,27.05 r0 top
T6 "" T07A 71.028,26.925 r0 top
TV1 "" PT61018PEL 85.065,56.533 r90 top locked
TV2 "" PT61018PEL 71.799,56.633 r90 top locked
VD1 "SMBJ6.5A" SMB(DO-214AA) 23.003,56.25 r0 top
VD2 "NUP4114UCLW1T2G (OnSemi, SC70)" DCK 46.819,75.063 r90 top
VD3 "SM712-02HTG" SOT-23A 18.498,71.027 r180 top value="SM712-02HTG (Littelfuse, SOT23-3)"
VD4 "Не устанавливать" SOD323(VISHAY) 55.688,30.896 r0 top
VD5 "SMBJ48CA-TR (STM, DO-214AA(SMB))" SMB(DO-214AA) 4.8,60.792 r180 top
VD6 "NUP4114UCLW1T2G (OnSemi, SC70)" DCK 86.485,48.636 r180 top
VD7 "NUP4114UCLW1T2G (OnSemi, SC70)" DCK 75.925,47.9 r225 top
VD8 "BZV55C36 (NXP, SOD80C)" DL-35 50.5,58.625 r270 top
VD20 "BAS716 (NXP, SOD-523)" SOD-523 82.029,36.925 r270 top
VT3 "BC807-40 (NXP, SOT-23)" SOT-23A 53.475,40.911 r270 top
VT4 "BC817-40L (ONSemi, SOT-23)" SOT-23A 47.169,56.265 r270 top
VT17 "BC817-40L (ONSemi, SOT-23)" SOT-23A 46.915,60.25 r180 top
XP1 "" 2EDGR-5.08-02P 10.88,76.1 r180 top locked
XP2 "Не устанавливать" JUMP1X2_2MM 8.8,37.729 r90 top
XP3 "PLD2-2 (Connfly,  DS1025-05-2*40P8BV1-B) (16 контактов)" PLD2-16 61.153,26.515 r180 top locked
XP4 "" PLD2-12 46.195,26.515 r180 top locked
XP5 "" PLD2-08 9.06,18.976 r0 top locked
XP6 "PLD2-2 (Connfly,  DS1025-05-2*40P8BV1-B) (16 контактов)" PLD2-16 61.153,18.976 r0 top locked
XP7 "" PLD2-12 46.195,18.976 r0 top locked
XS1 "PBD1,27-2-5SM-G-4,5mm (Connfly, DS1065-05-2*5S8BSS" PBD1.27-10S_small 14.775,43.715 r90 top locked
XS2 "" USB4105-GF-A-xxx 46.89,83.95 r180 top locked
XS3 "" MJ881B-BX11-HRVL11-X 82.84,75.21 r180 top locked
XS4 "" MJ881B-BX11-HRVL11-X 64.001,75.21 r180 top locked
XT2 "" 15EDGRC-3.5-03P 24.56,78.451 r180 top locked

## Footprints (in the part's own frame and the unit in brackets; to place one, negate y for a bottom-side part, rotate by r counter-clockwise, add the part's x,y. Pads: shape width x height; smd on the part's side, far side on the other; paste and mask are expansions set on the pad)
2EDGR-5.08-02P [mm] "THT"
  oval 2.2x3.2 hole 1.6: 1(0,0) 2(5.08,0)
  silkscreen extent -2.54,-10.5 7.62,2.8, body extent -2.54,-10.6 7.62,1.5, height 8.47
15EDGRC-3.5-03P [mm] "THT"
  round 2 hole 1.4: 1(0,0) 3(7,0)
  round 1.4 / inner round 2 / far side round 2 hole 1.4: 2(3.5,0)
  silkscreen extent -2.31,-8.15 9.3,2.9, body extent -2.15,-8 9.15,1.2, height 7.25
C0402 [mm] "SMD"
  rect 0.6x0.65 smd paste-25.4: 1(-0.5,0) 2(0.5,0)
  body extent -0.5,-0.3 0.5,0.3, height 0.49
CC0603-KL [mm] "SMD"
  rect 0.75x1 smd paste-25.4: 1(-0.68,0) 2(0.68,0)
  silkscreen extent -1.23,-0.68 1.23,0.68, body extent -0.8,-0.4 0.8,0.4, height 0.9
CC0805-KL [mm] "SMD"
  rect 1.016x1.4 smd paste-25.4: 1(-0.9,0) 2(0.9,0)
  silkscreen extent -1.61,-0.9 1.61,0.9, body extent -1,-0.62 1,0.63, height 1
CC1206-KL [mil] "SMD"
  rect 40x70 smd paste-1000: 1(-59.09,0) 2(59.09,0)
  silkscreen extent -87,-43 87,43, body extent -63,-31 63,31, height 39
DCK [mm] "SMD"
  rrect50% 0.85x0.35 smd: 1(-1.1,0.65) 2(-1.1,0) 3(-1.1,-0.65) 4(1.1,-0.65) 5(1.1,0) 6(1.1,0.65)
  silkscreen extent -1.22,-1.1 0.3,1.5, body extent -1.2,-1.07 1.2,1.07, height 1.1
DL-35 [mm] "SMD"
  rect 1.3x1.8 smd paste-25.4: 1(-1.65,0) 2(1.65,0)
  silkscreen extent -2.45,-1.05 2.45,1.05, body extent -1.8,-0.87 1.8,0.87, height 1.76
F0505S-1W [mm] "THT"
  rect 1.8x1.8 hole 1.1: 1(0,0)
  round 1.8 hole 1.1: 2(2.54,0) 5(10.16,0) 7(15.24,0)
  silkscreen extent -2.2,-4.95 17.8,1.45, body extent -2,-4.75 17.6,1.25, height 10.01
FXO2520 [mm] "SMD"
  rect 1x1 smd paste-25.4: 1(-0.825,-0.625) 2(0.825,-0.625) 3(0.825,0.625) 4(-0.825,0.625)
  silkscreen extent -1.55,-2.01 1.55,1.35, body extent -1.25,-1 1.25,1, height 0.83
"HS LC-H-D2C/ R2XC2-2,54" [mm] "THT"
  round 1.2 hole 1.2 unplated: MH(0,-4.326) MH(0,2.574) MH(2.54,-4.326) MH(2.54,2.574)
  silkscreen extent -1.61,-5.33 4.29,4.32, body extent -1.51,-5.22 4.21,6.63, height 6.05
HT19-2132 [mm] "SMD"
  rect 0.8x0.8 smd paste-25.4: A(0.75,0) C(-0.75,0)
  silkscreen extent -1.47,-0.58 1.33,0.58, body extent -0.8,-0.4 0.8,0.4, height 0.6
JUMP1X2_2MM [mm] "THT"
  rect 1.3x1.3 hole 0.8: 1(0,0)
  round 1.3 hole 0.8: 2(2,0)
  silkscreen extent -1,-1.2 3,1.2, body extent -1,-1 3,1, height 7.05
JY_8-A2 [mm] "THT"
  rect 1.5x1.5 hole 0.85: 1(-3.75,0)
  round 1.5 hole 0.85: 2(3.75,0)
  silkscreen extent -4.47,-2.51 4.5,2.49, body extent -4.05,-2.59 4.02,2.05, height 10
KOTB30 [mm]
  round 3 hole 3 unplated: 1(0,0)
  Top Layer keep-out circle w0.1: c0,0 r2.15
  Bottom Layer keep-out circle w0.1: c0,0 r2.15
L0603 [mm] "SMD"
  rect 0.75x1 smd paste-25.4: 1(-0.775,0) 2(0.775,0)
  silkscreen extent -1.32,-0.68 1.33,0.68, body extent -0.8,-0.41 0.8,0.41, height 0.81
L0805 [mm] "SMD"
  rect 1.05x1.4 smd paste-25.4: 1(-0.95,0) 2(0.95,0)
  silkscreen extent -1.7,-0.9 1.7,0.9, body extent -1,-0.61 1,0.61, height 1.26
L1206 [mil] "SMD"
  rect 65x82 smd paste-1000: 1(-60,0) 2(60,0)
  silkscreen extent -103,-50 102,50, body extent -63,-32 63,32, height 44
MJ881B-BX11-HRVL11-X [mm] "THT"
  round 1.5 hole 0.9: 1(3.57,4.51) 2(2.55,2.51) 3(1.53,4.51) 4(0.51,2.51) 5(-0.51,4.51) 6(-1.53,2.51) 7(-2.55,4.51) 8(-3.57,2.51)
  round 1.2 / inner round 1.6 / far side round 1.6 hole 1: 9(-6.86,7.49) 10(-4.57,7.49) 11(4.57,7.49) 12(6.86,7.49)
  oval 1.6x3 hole 1 slot 2.4 at 90 deg: 13(-8.1,-1.49) 13(-8.1,-7.49) 13(8.1,-1.49) 13(8.1,-7.49)
  silkscreen extent -8.23,-5.65 8.23,8.91, body extent -8.21,-12.08 8.22,8.91, height 8.52
MMTF32 [mm] "THT"
  round 0.85 hole 0.5: 1(0,0) 2(0.862,-0.7)
  silkscreen extent -9,-1.35 0.24,0.65, body extent -9,-1.35 1,0.65, height 2
NX3215SA [mm] "SMD"
  rect 1x1.8 smd paste-25.4: 1(-1.25,0) 2(1.252,0)
  silkscreen extent -1.9,-1.05 1.9,1.05, body extent -1.65,-0.8 1.65,0.8, height 0.9
PBD1.27-10S_small [mm] "SMD"
  rrect50% 0.76x2.05 smd: 1(-2.54,-1.775) 2(-2.54,1.775) 3(-1.27,-1.775) 4(-1.27,1.775) 5(0,-1.775) 6(0,1.775) 7(1.27,-1.775) 8(1.27,1.775) 9(2.54,-1.775) 10(2.54,1.775)
  silkscreen extent -3.72,-2.48 3.47,1.55, body extent -3.4,-2.24 3.41,2.26, height 4.5
PLD2-08 [mm] "THT"
  rect 1.3x1.3 hole 0.8: 1(-3,-1)
  round 1.3 hole 0.8: 2(-3,1) 5(1,-1) 6(1,1) 7(3,-1) 8(3,1)
  round 0 hole 0.8 unplated: 3(-1,-1) 4(-1,1)
  silkscreen extent -4.1,-2.85 4.1,2.1, body extent -4,-2 4,2, height 6
PLD2-12 [mm] "THT"
  rect 1.3x1.3 hole 0.8: 1(-5,-1)
  round 1.3 hole 0.8: 2(-5,1) 3(-3,-1) 4(-3,1) 5(-1,-1) 6(-1,1) 7(1,-1) 8(1,1) 9(3,-1) 10(3,1) 11(5,-1) 12(5,1)
  silkscreen extent -6.1,-2.85 6.1,2.1, body extent -6,-2 6,2, height 6
PLD2-16 [mm] "THT"
  rect 1.3x1.3 hole 0.8: 1(-7,-1)
  round 1.3 hole 0.8: 2(-7,1) 3(-5,-1) 4(-5,1) 5(-3,-1) 6(-3,1) 7(-1,-1) 8(-1,1) 9(1,-1) 10(1,1) 11(3,-1) 12(3,1) 13(5,-1) 14(5,1) 15(7,-1) 16(7,1)
  silkscreen extent -8.1,-2.85 8.1,2.1, body extent -8,-2 8,2, height 6
PT61018PEL [mm] "SMD"
  rrect50% 1.9x0.76 smd paste-25.4: 1(-4.382,4.445) 2(-4.383,3.175) 3(-4.382,1.905) 4(-4.382,0.635) 5(-4.382,-0.635) 6(-4.382,-1.905) 7(-4.383,-3.175) 8(-4.382,-4.445) 9(4.383,-4.445) 10(4.383,-3.175) 11(4.383,-1.905) 12(4.383,-0.635) 13(4.383,0.635) 14(4.383,1.905) 15(4.383,3.175) 16(4.383,4.445)
  silkscreen extent -5.96,-6.42 4.64,6.44, body extent -4.7,-6.35 4.7,6.35, height 5.6
R0402 [mm] "SMD"
  rect 0.65x0.65 smd paste-25.4: 1(-0.45,0) 2(0.45,0)
  body extent -0.5,-0.27 0.5,0.28, height 0.4
RC0603-KL [mm] "SMD"
  rect 0.75x1 smd paste-25.4: 1(-0.68,0) 2(0.68,0)
  silkscreen extent -1.21,-0.65 1.21,0.65, body extent -0.8,-0.42 0.8,0.43, height 0.6
RC1206-KL [mil] "SMD"
  rect 40x70 smd paste-1000: 1(-59.05,0) 2(59.13,0)
  silkscreen extent -85,-41 85,41, body extent -63,-31 63,32, height 28
SMB(DO-214AA) [mm] "SMD"
  rect 2x2.2 smd paste-25.4: 1(-2.205,0) 2(2.205,0)
  silkscreen extent -3.42,-2.06 3.42,2.05, body extent -2.75,-1.95 2.75,1.95, height 2.45
SO8 [mil] "SMD"
  rect 80x26 smd paste-1000: 1(-110,75) 2(-110,25) 3(-110,-25) 4(-110,-75) 5(110,-75) 6(110,-25) 7(110,25) 8(110,75)
  silkscreen extent -157,-115 157,120, body extent -114,-96 114,97, height 57
SO-16_W [mil] "SMD"
  rect 71x25.5 smd paste-1000: 1(-197.5,175) 2(-197.5,125) 3(-197.5,75) 4(-197.5,25) 5(-197.5,-25) 6(-197.5,-75) 7(-197.5,-125) 8(-197.5,-175) 9(197.5,-175) 10(197.5,-125) 11(197.5,-75) 12(197.5,-25) 13(197.5,25) 14(197.5,75) 15(197.5,125) 16(197.5,175)
  silkscreen extent -202,-211 154,216, body extent -210,-207 210,207, height 104
SOD323(VISHAY) [mm] "SMD"
  rect 0.6x0.6 smd paste-25.4: 1(-1.1,0) 2(1.1,0)
  silkscreen extent -1.62,-0.8 1.83,0.8, body extent -1.35,-0.67 1.35,0.68, height 1.12
SOD-523 [mm] "SMD"
  rect 0.9x0.5 smd paste-25.4: 1(0.8,0) 2(-0.8,0)
  silkscreen extent -1.7,-0.52 1.4,0.52, body extent -0.91,-0.42 0.92,0.42, height 0.71
SOP127P790X216-8N [mm] "SMD"
  oval 1.7x0.6 smd: 1(-3.55,1.905) 2(-3.55,0.635) 3(-3.55,-0.635) 4(-3.55,-1.905) 5(3.55,-1.905) 6(3.55,-0.635) 7(3.55,0.635) 8(3.55,1.905)
  silkscreen extent -3.68,-2.7 2.3,2.88, body extent -3.95,-2.7 3.95,2.7, height 2.16
SOT23-5 [mm] "SMD"
  rect 1.2x0.6 smd paste-25.4: 1(1.25,-0.95) 2(1.25,0) 3(1.25,0.95) 4(-1.25,0.95) 5(-1.25,-0.95)
  silkscreen extent -2.03,-1.45 2.03,1.45, body extent -1.5,-1.5 1.5,1.5, height 1.46
SOT65P210-5N [mm] "SMD"
  rrect50% 1x0.4 smd: 1(-1.1,0.65) 2(-1.1,0) 3(-1.1,-0.65) 4(1.1,-0.65) 5(1.1,0.65)
  silkscreen extent -2.18,-1 0.28,1, body extent -1.14,-1.13 1.14,1.12, height 1.1
SOT-23A [mil] "SMD"
  rect 36x40 smd paste-1000: 1(-40,-47) 2(40,-47) 3(0,47)
  silkscreen extent -66,-77 66,78, body extent -59,-49 59,49, height 43
T07A [mm]
  round 0.75 smd paste-25.4: 1(0,0)
T17A [mm]
  round 0.991 smd paste-25.4: 1(0,0)
"TE IM03GR Gul wings" [mm] "SMD"
  rect 0.8x2.15 smd paste-20: 1(-3.8,-3.175) 2(-0.6,-3.175) 3(1.59,-3.175) 4(3.8,-3.175) 5(3.8,3.175) 6(1.6,3.175) 7(-0.6,3.175) 8(-3.8,3.175)
  silkscreen extent -5,-5.01 5.05,3.3, body extent -5.03,-3.75 5.05,3.75, height 5.65
TP-1113 [mm] "SMD"
  rect 1.4x1.2 smd paste-20: 1(1.7,-2.775) 1(1.7,2.775) 2(-1.7,-2.775) 2(-1.7,2.775)
  rrect50% 1.4x1.2 smd: 1(1.7,-2.775) 1(1.7,2.775) 2(-1.7,-2.775) 2(-1.7,2.775)
  round 1 hole 1 unplated: MH(-1.5,0) MH(1.5,0)
  silkscreen extent -3.1,-2 4.65,2, body extent -3.2,-3.1 4.5,3.1, height 2.1
TSQFP50P900X900X160-48N [mm] "SMD"
  rrect50% 1.4x0.3 smd: 1(-4.2,2.75) 2(-4.2,2.25) 3(-4.2,1.75) 4(-4.2,1.25) 5(-4.2,0.75) 6(-4.2,0.25) 7(-4.2,-0.25) 8(-4.2,-0.75) 9(-4.2,-1.25) 10(-4.2,-1.75) 11(-4.2,-2.25) 12(-4.2,-2.75) 25(4.2,-2.75) 26(4.2,-2.25) 27(4.2,-1.75) 28(4.2,-1.25) 29(4.2,-0.75) 30(4.2,-0.25) 31(4.2,0.25) 32(4.2,0.75) 33(4.2,1.25) 34(4.2,1.75) 35(4.2,2.25) 36(4.2,2.75)
  rrect50% 0.3x1.4 smd: 13(-2.75,-4.2) 14(-2.25,-4.2) 15(-1.75,-4.2) 16(-1.25,-4.2) 17(-0.75,-4.2) 18(-0.25,-4.2) 19(0.25,-4.2) 20(0.75,-4.2) 21(1.25,-4.2) 22(1.75,-4.2) 23(2.25,-4.2) 24(2.75,-4.2) 37(2.75,4.2) 38(2.25,4.2) 39(1.75,4.2) 40(1.25,4.2) 41(0.75,4.2) 42(0.25,4.2) 43(-0.25,4.2) 44(-0.75,4.2) 45(-1.25,4.2) 46(-1.75,4.2) 47(-2.25,4.2) 48(-2.75,4.2)
  silkscreen extent -5.71,-5.66 5.7,5.66, body extent -4.5,-4.5 4.5,4.5, height 1.6
TSQFP50P1600X1600X160-100N [mm] "SMD"
  oval 1.45x0.3 smd: 1(-7.725,6) 2(-7.725,5.5) 3(-7.725,5) 4(-7.725,4.5) 5(-7.725,4) 6(-7.725,3.5) 7(-7.725,3) 8(-7.725,2.5) 9(-7.725,2) 10(-7.725,1.5) 11(-7.725,1) 12(-7.725,0.5) 13(-7.725,0) 14(-7.725,-0.5) 15(-7.725,-1) 16(-7.725,-1.5) 17(-7.725,-2) 18(-7.725,-2.5) 19(-7.725,-3) 20(-7.725,-3.5) 21(-7.725,-4) 22(-7.725,-4.5) 23(-7.725,-5) 24(-7.725,-5.5) 25(-7.725,-6) 51(7.725,-6) 52(7.725,-5.5) 53(7.725,-5) 54(7.725,-4.5) 55(7.725,-4) 56(7.725,-3.5) 57(7.725,-3) 58(7.725,-2.5) 59(7.725,-2) 60(7.725,-1.5) 61(7.725,-1) 62(7.725,-0.5) 63(7.725,0) 64(7.725,0.5) 65(7.725,1) 66(7.725,1.5) 67(7.725,2) 68(7.725,2.5) 69(7.725,3) 70(7.725,3.5) 71(7.725,4) 72(7.725,4.5) 73(7.725,5) 74(7.725,5.5) 75(7.725,6)
  oval 0.3x1.45 smd: 26(-6,-7.725) 27(-5.5,-7.725) 28(-5,-7.725) 29(-4.5,-7.725) 30(-4,-7.725) 31(-3.5,-7.725) 32(-3,-7.725) 33(-2.5,-7.725) 34(-2,-7.725) 35(-1.5,-7.725) 36(-1,-7.725) 37(-0.5,-7.725) 38(0,-7.725) 39(0.5,-7.725) 40(1,-7.725) 41(1.5,-7.725) 42(2,-7.725) 43(2.5,-7.725) 44(3,-7.725) 45(3.5,-7.725) 46(4,-7.725) 47(4.5,-7.725) 48(5,-7.725) 49(5.5,-7.725) 50(6,-7.725) 76(6,7.725) 77(5.5,7.725) 78(5,7.725) 79(4.5,7.725) 80(4,7.725) 81(3.5,7.725) 82(3,7.725) 83(2.5,7.725) 84(2,7.725) 85(1.5,7.725) 86(1,7.725) 87(0.5,7.725) 88(0,7.725) 89(-0.5,7.725) 90(-1,7.725) 91(-1.5,7.725) 92(-2,7.725) 93(-2.5,7.725) 94(-3,7.725) 95(-3.5,7.725) 96(-4,7.725) 97(-4.5,7.725) 98(-5,7.725) 99(-5.5,7.725) 100(-6,7.725)
  silkscreen extent -9.11,-9.06 9.11,9.06, body extent -8,-8 8,8, height 1.6
USB4105-GF-A-xxx [mm] "SMD"
  rect 0.6x1.15 smd paste-20: A1_B12(-3.2,4.755) A4_B9(-2.4,4.755) B1_A12(3.2,4.755) B4_A9(2.4,4.755)
  rect 0.3x1.15 smd paste-20: A5(-1.25,4.755) A6(-0.25,4.755) A7(0.25,4.755) A8(1.25,4.755) B5(1.75,4.755) B6(0.75,4.755) B7(-0.75,4.755) B8(-1.75,4.755)
  round 0.65 hole 0.65 unplated: MH1(-2.89,3.68) MH2(2.89,3.68)
  oval 1.05x2.1 hole 0.6 slot 1.7 at 90 deg: SHELL(-4.32,4.18) SHELL(4.32,4.18)
  oval 1x2 hole 0.6 slot 1.4 at 90 deg: SHELL(-4.32,0) SHELL(4.32,0)
  silkscreen extent -4.89,-2.7 4.89,3.1, body extent -4.47,-2.6 4.47,5.1, height 3.26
